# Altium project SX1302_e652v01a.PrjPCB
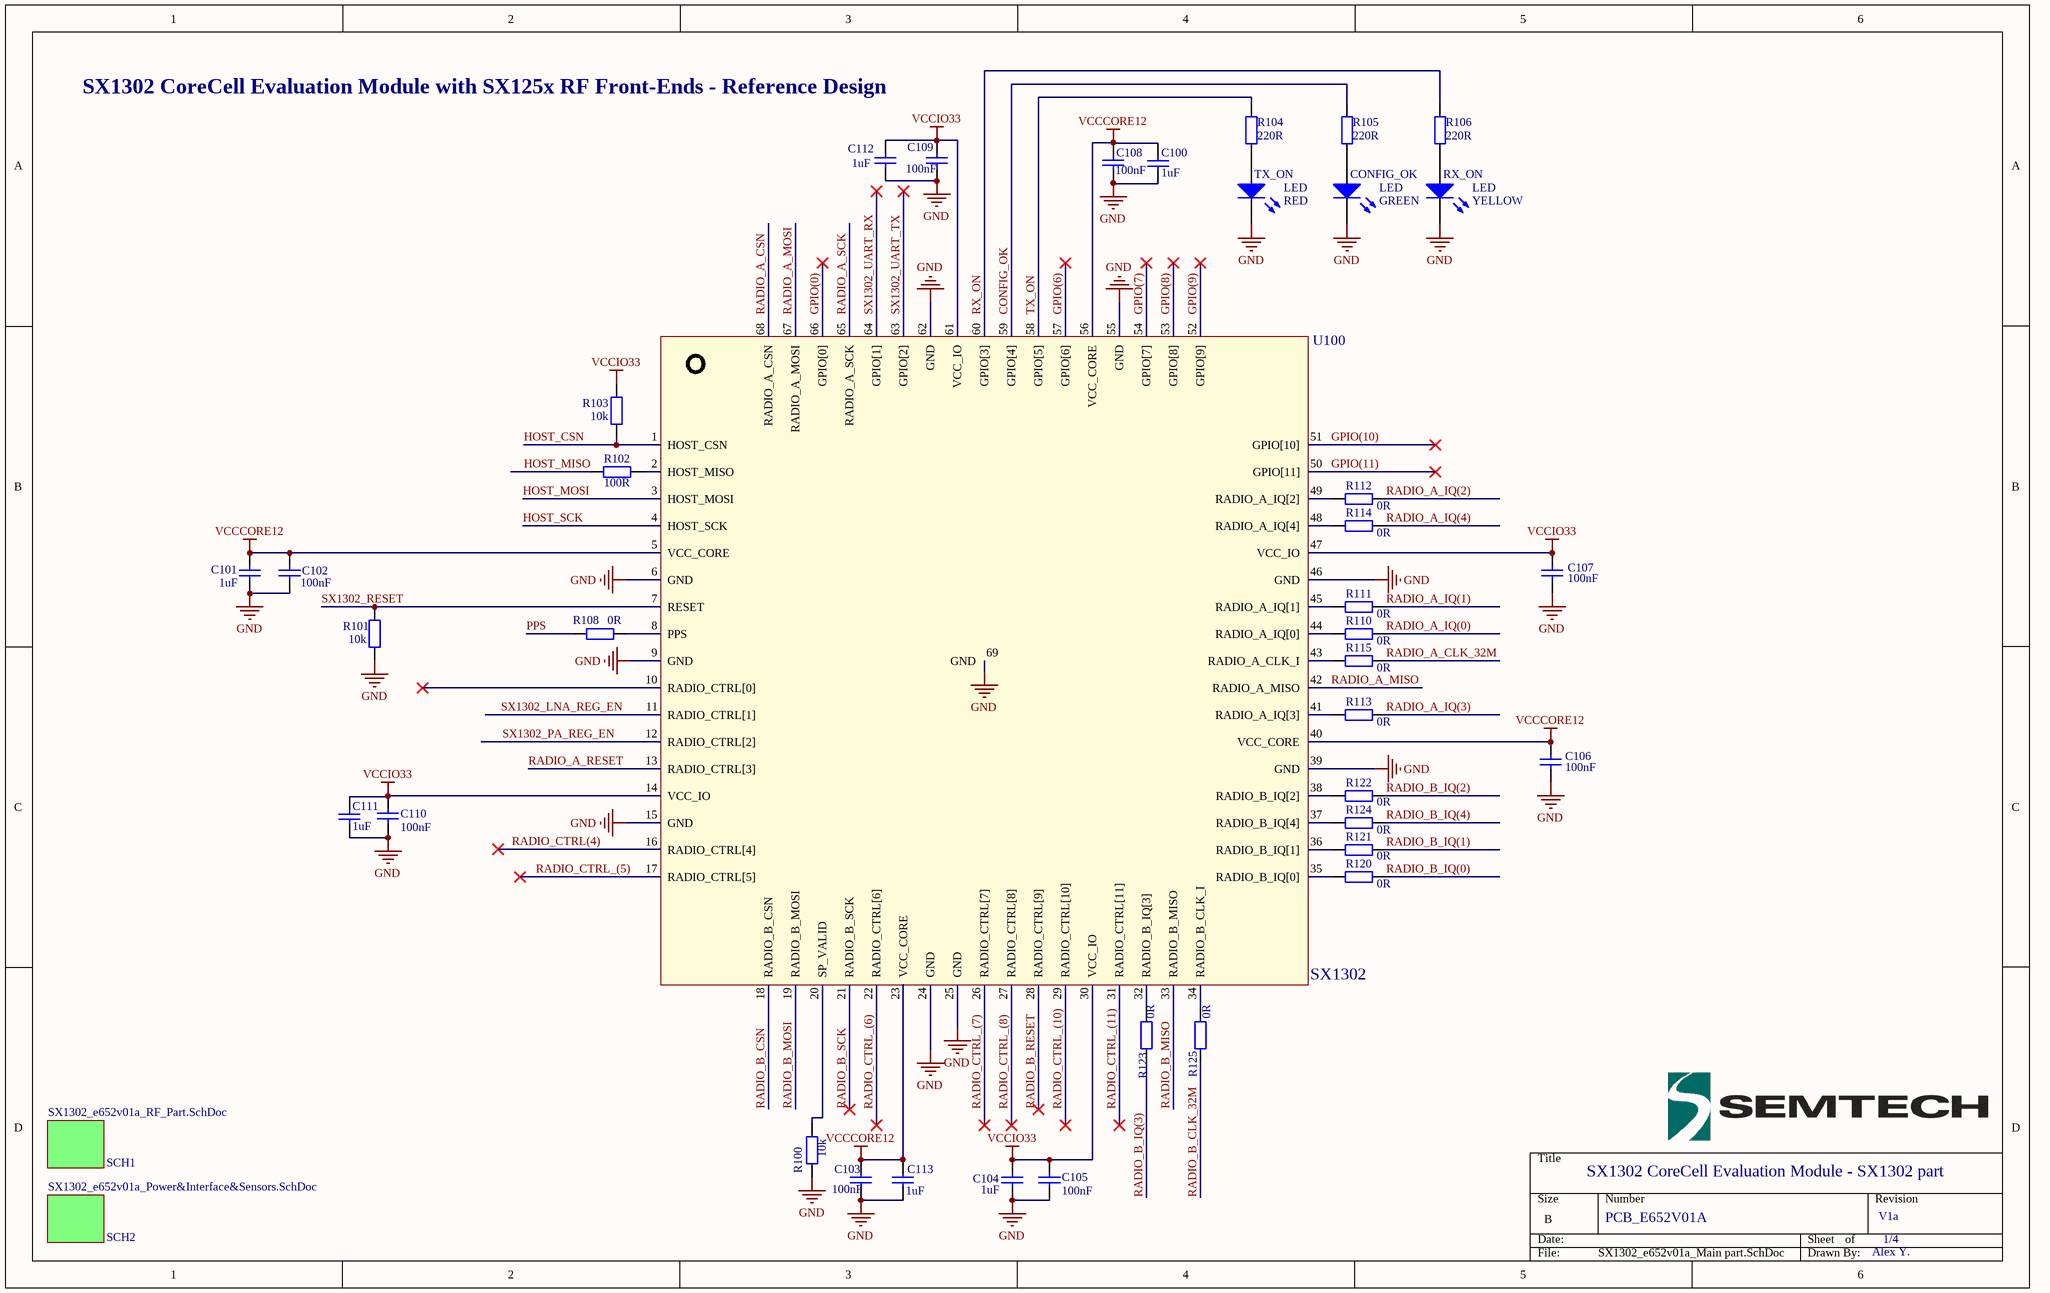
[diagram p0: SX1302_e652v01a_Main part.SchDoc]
4 sheets, 264 parts. Net scope: global (net labels, ports and power ports of the same name join across sheets).
Board file: SX1302_e652v01a.PcbDoc
Sheets:
  SX1302_e652v01a_Main part.SchDoc
    SCH2 = SX1302_e652v01a_Power&Interface&Sensors.SchDoc
    SCH1 = SX1302_e652v01a_RF_Part.SchDoc
       = SX1302_e652v01a_RF_PA.SchDoc

## Sheet SX1302_e652v01a_Main part.SchDoc: SX1302
size B; Author: Alex; DrawnBy: AYang; DocumentNumber: 1; SheetNumber: 1; SheetTotal: 5; PageSetup: Record=PageOptions¦CenterHorizontal=True¦CenterVertical=True¦PrintScale=0.72¦XCorrection=1.00¦YCorrection=1.00¦PrintKind=0¦BorderSize=5000000¦LeftOffset=0¦BottomOffset=0¦Orientation=2¦PaperLength=1000¦PaperWidth=1000¦Scale=100¦PaperSource=7¦PrintQuality=-4¦MediaType=1¦DitherType=10¦PaperKind=Letter¦PrintScaleMode=1

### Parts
C100  value 1uF  [rlc_402_smd_small]  (hidden comment: Cap)
C101  value 1uF  [rlc_402_smd_small]  (hidden comment: Cap)
C102  value 100nF  [rlc_201_smd_small]  (hidden comment: Cap)
C103  value 100nF  [rlc_201_smd_small]  (hidden comment: Cap)
C104  value 1uF  [rlc_402_smd_small]  (hidden comment: Cap)
C105  value 100nF  [rlc_201_smd_small]  (hidden comment: Cap)
C106  value 100nF  [rlc_201_smd_small]  (hidden comment: Cap)
C107  value 100nF  [rlc_201_smd_small]  (hidden comment: Cap)
C108  value 100nF  [rlc_201_smd_small]  (hidden comment: Cap)
C109  value 100nF  [rlc_201_smd_small]  (hidden comment: Cap)
C110  value 100nF  [rlc_201_smd_small]  (hidden comment: Cap)
C111  value 1uF  [rlc_402_smd_small]  (hidden comment: Cap)
C112  value 1uF  [rlc_402_smd_small]  (hidden comment: Cap)
C113  value 1uF  [rlc_402_smd_small]  (hidden comment: Cap)
CONFIG_OK  LED  Type: GREEN  [CD1005-0402]
R100  value 10k  [rlc_201_smd_small]  (hidden comment: Resistor)
R101  value 10k  [rlc_201_smd_small]  (hidden comment: Resistor)
R102  value 100R  [rlc_201_smd_small]  (hidden comment: Resistor)
R103  value 10k  [rlc_201_smd_small]  (hidden comment: Resistor)
R104  value 220R  [rlc_402_smd]  (hidden comment: Resistor)
R105  value 220R  [rlc_402_smd]  (hidden comment: Resistor)
R106  value 220R  [rlc_402_smd]  (hidden comment: Resistor)
R108  value 0R  [rlc_201_smd_small]  (hidden comment: Resistor)
R110  value 0R  [rlc_201_smd_small]  (hidden comment: Resistor)
R111  value 0R  [rlc_201_smd_small]  (hidden comment: Resistor)
R112  value 0R  [rlc_201_smd_small]  (hidden comment: Resistor)
R113  value 0R  [rlc_201_smd_small]  (hidden comment: Resistor)
R114  value 0R  [rlc_201_smd_small]  (hidden comment: Resistor)
R115  value 0R  [rlc_201_smd_small]  (hidden comment: Resistor)
R120  value 0R  [rlc_201_smd_small]  (hidden comment: Resistor)
R121  value 0R  [rlc_201_smd_small]  (hidden comment: Resistor)
R122  value 0R  [rlc_201_smd_small]  (hidden comment: Resistor)
R123  value 0R  [rlc_201_smd_small]  (hidden comment: Resistor)
R124  value 0R  [rlc_201_smd_small]  (hidden comment: Resistor)
R125  value 0R  [rlc_201_smd_small]  (hidden comment: Resistor)
RX_ON  LED  Type: YELLOW  [CD1005-0402]
TX_ON  LED  Type: RED  [CD1005-0402]
U100  SX1302  [vqfn68_7x7mm]

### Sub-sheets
SCH1 = SX1302_e652v01a_RF_Part.SchDoc: no entries
SCH2 = SX1302_e652v01a_Power&Interface&Sensors.SchDoc: no entries

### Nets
GND: C100.1 C101.1 C102.1 C103.1 C104.1 C105.1 C106.1 C107.1 C108.1 C109.1 C110.1 C111.1 C112.1 C113.1 CONFIG_OK.2(K) R100.1 R101.1 RX_ON.2(K) TX_ON.2(K) U100.6(GND) U100.9(GND) U100.15(GND) U100.24(GND) U100.25(GND) U100.39(GND) U100.46(GND) U100.55(GND) U100.62(GND) U100.69(GND)
VCCCORE12: C100.2 C101.2 C102.2 C103.2 C106.2 C108.2 C113.2 U100.5(VCC_CORE) U100.23(VCC_CORE) U100.40(VCC_CORE) U100.56(VCC_CORE)
VCCIO33: C104.2 C105.2 C107.2 C109.2 C110.2 C111.2 C112.2 R103.2 U100.14(VCC_IO) U100.30(VCC_IO) U100.47(VCC_IO) U100.61(VCC_IO)
CONFIG_OK: R105.2 U100.59(GPIO[4])
GPIO(0): U100.66(GPIO[0])
GPIO(6): U100.57(GPIO[6])
GPIO(7): U100.54(GPIO[7])
GPIO(8): U100.53(GPIO[8])
GPIO(9): U100.52(GPIO[9])
GPIO(10): U100.51(GPIO[10])
GPIO(11): U100.50(GPIO[11])
HOST_CSN: R103.1 U100.1(HOST_CSN)
HOST_MISO: R102.2
HOST_MOSI: U100.3(HOST_MOSI)
HOST_SCK: U100.4(HOST_SCK)
PPS: R108.1
RADIO_A_CLK_32M: R115.2
RADIO_A_CSN: U100.68(RADIO_A_CSN)
RADIO_A_IQ(0): R110.2
RADIO_A_IQ(1): R111.2
RADIO_A_IQ(2): R112.2
RADIO_A_IQ(3): R113.2
RADIO_A_IQ(4): R114.2
RADIO_A_MISO: U100.42(RADIO_A_MISO)
RADIO_A_MOSI: U100.67(RADIO_A_MOSI)
RADIO_A_RESET: U100.13(RADIO_CTRL[3])
RADIO_A_SCK: U100.65(RADIO_A_SCK)
RADIO_B_CLK_32M: R125.1
RADIO_B_CSN: U100.18(RADIO_B_CSN)
RADIO_B_IQ(0): R120.2
RADIO_B_IQ(1): R121.2
RADIO_B_IQ(2): R122.2
RADIO_B_IQ(3): R123.1
RADIO_B_IQ(4): R124.2
RADIO_B_MISO: U100.33(RADIO_B_MISO)
RADIO_B_MOSI: U100.19(RADIO_B_MOSI)
RADIO_B_RESET: U100.28(RADIO_CTRL[9])
RADIO_B_SCK: U100.21(RADIO_B_SCK)
RADIO_CTRL(4): U100.16(RADIO_CTRL[4])
RADIO_CTRL_(5): U100.17(RADIO_CTRL[5])
RADIO_CTRL_(6): U100.22(RADIO_CTRL[6])
RADIO_CTRL_(7): U100.26(RADIO_CTRL[7])
RADIO_CTRL_(8): U100.27(RADIO_CTRL[8])
RADIO_CTRL_(10): U100.29(RADIO_CTRL[10])
RADIO_CTRL_(11): U100.31(RADIO_CTRL[11])
RX_ON: R106.2 U100.60(GPIO[3])
SX1302_LNA_REG_EN: U100.11(RADIO_CTRL[1])
SX1302_PA_REG_EN: U100.12(RADIO_CTRL[2])
SX1302_RESET: R101.2 U100.7(RESET)
SX1302_UART_RX: U100.64(GPIO[1])
SX1302_UART_TX: U100.63(GPIO[2])
TX_ON: R104.2 U100.58(GPIO[5])
NetCONFIG_OK_1: CONFIG_OK.1(A) R105.1
NetR100_2: R100.2 U100.20(SP_VALID)
NetR102_1: R102.1 U100.2(HOST_MISO)
NetR104_1: R104.1 TX_ON.1(A)
NetR106_1: R106.1 RX_ON.1(A)
NetR108_2: R108.2 U100.8(PPS)
NetR110_1: R110.1 U100.44(RADIO_A_IQ[0])
NetR111_1: R111.1 U100.45(RADIO_A_IQ[1])
NetR112_1: R112.1 U100.49(RADIO_A_IQ[2])
NetR113_1: R113.1 U100.41(RADIO_A_IQ[3])
NetR114_1: R114.1 U100.48(RADIO_A_IQ[4])
NetR115_1: R115.1 U100.43(RADIO_A_CLK_I)
NetR120_1: R120.1 U100.35(RADIO_B_IQ[0])
NetR121_1: R121.1 U100.36(RADIO_B_IQ[1])
NetR122_1: R122.1 U100.38(RADIO_B_IQ[2])
NetR123_2: R123.2 U100.32(RADIO_B_IQ[3])
NetR124_1: R124.1 U100.37(RADIO_B_IQ[4])
NetR125_2: R125.2 U100.34(RADIO_B_CLK_I)

Not connected (* = marked no-connect by the designer): U100 10(RADIO_CTRL[0])*

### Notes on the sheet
- SX1302 CoreCell Evaluation Module with SX125x RF Front-Ends - Reference Design
- SX1302 CoreCell Evaluation Module - SX1302 part
- PCB_E652V01A
- V1a
- 1/4
- Alex Y.

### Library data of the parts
C100-C113 = Cap: Capacitor SMD
R100-R106 R108 R110-R115 R120-R125 = Resistor: Resistor SMD - IEC symbol version
U100 = SX1302: SX1302 - Base Band Processor for Data Concentrator for Long Range Communication Network;

## Sheet SX1302_e652v01a_Power&Interface&Sensors.SchDoc
size A2; DrawnBy: EMr; DocumentNumber: 2; SheetNumber: 2; SheetTotal: 5; PageSetup: Record=PageOptions¦CenterHorizontal=True¦CenterVertical=True¦PrintScale=0.72¦XCorrection=1.00¦YCorrection=1.00¦PrintKind=0¦BorderSize=5000000¦LeftOffset=0¦BottomOffset=0¦Orientation=2¦PaperLength=1000¦PaperWidth=1000¦Scale=100¦PaperSource=7¦PrintQuality=-4¦MediaType=1¦DitherType=10¦PaperKind=Letter¦PrintScaleMode=1
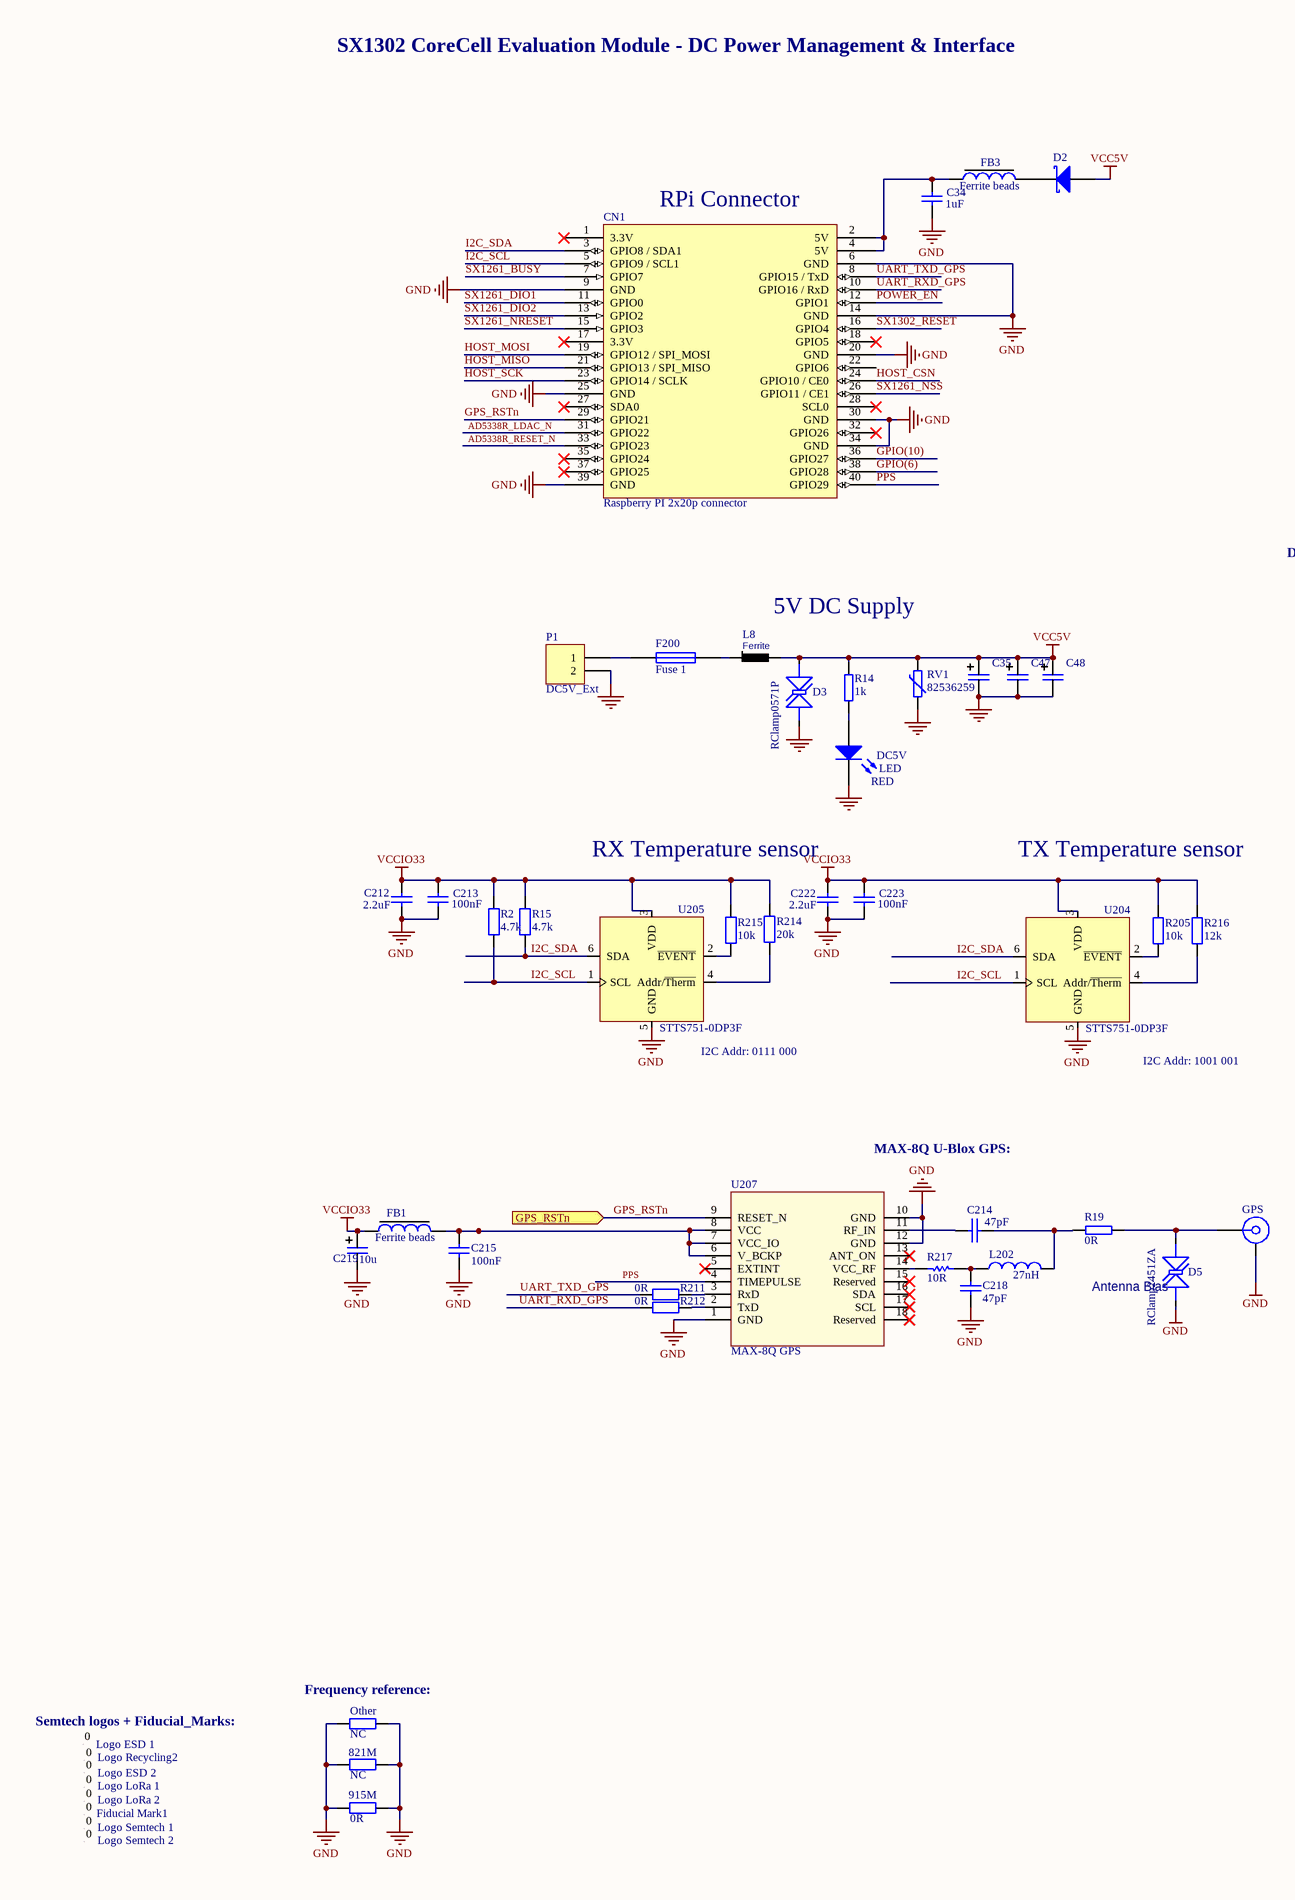
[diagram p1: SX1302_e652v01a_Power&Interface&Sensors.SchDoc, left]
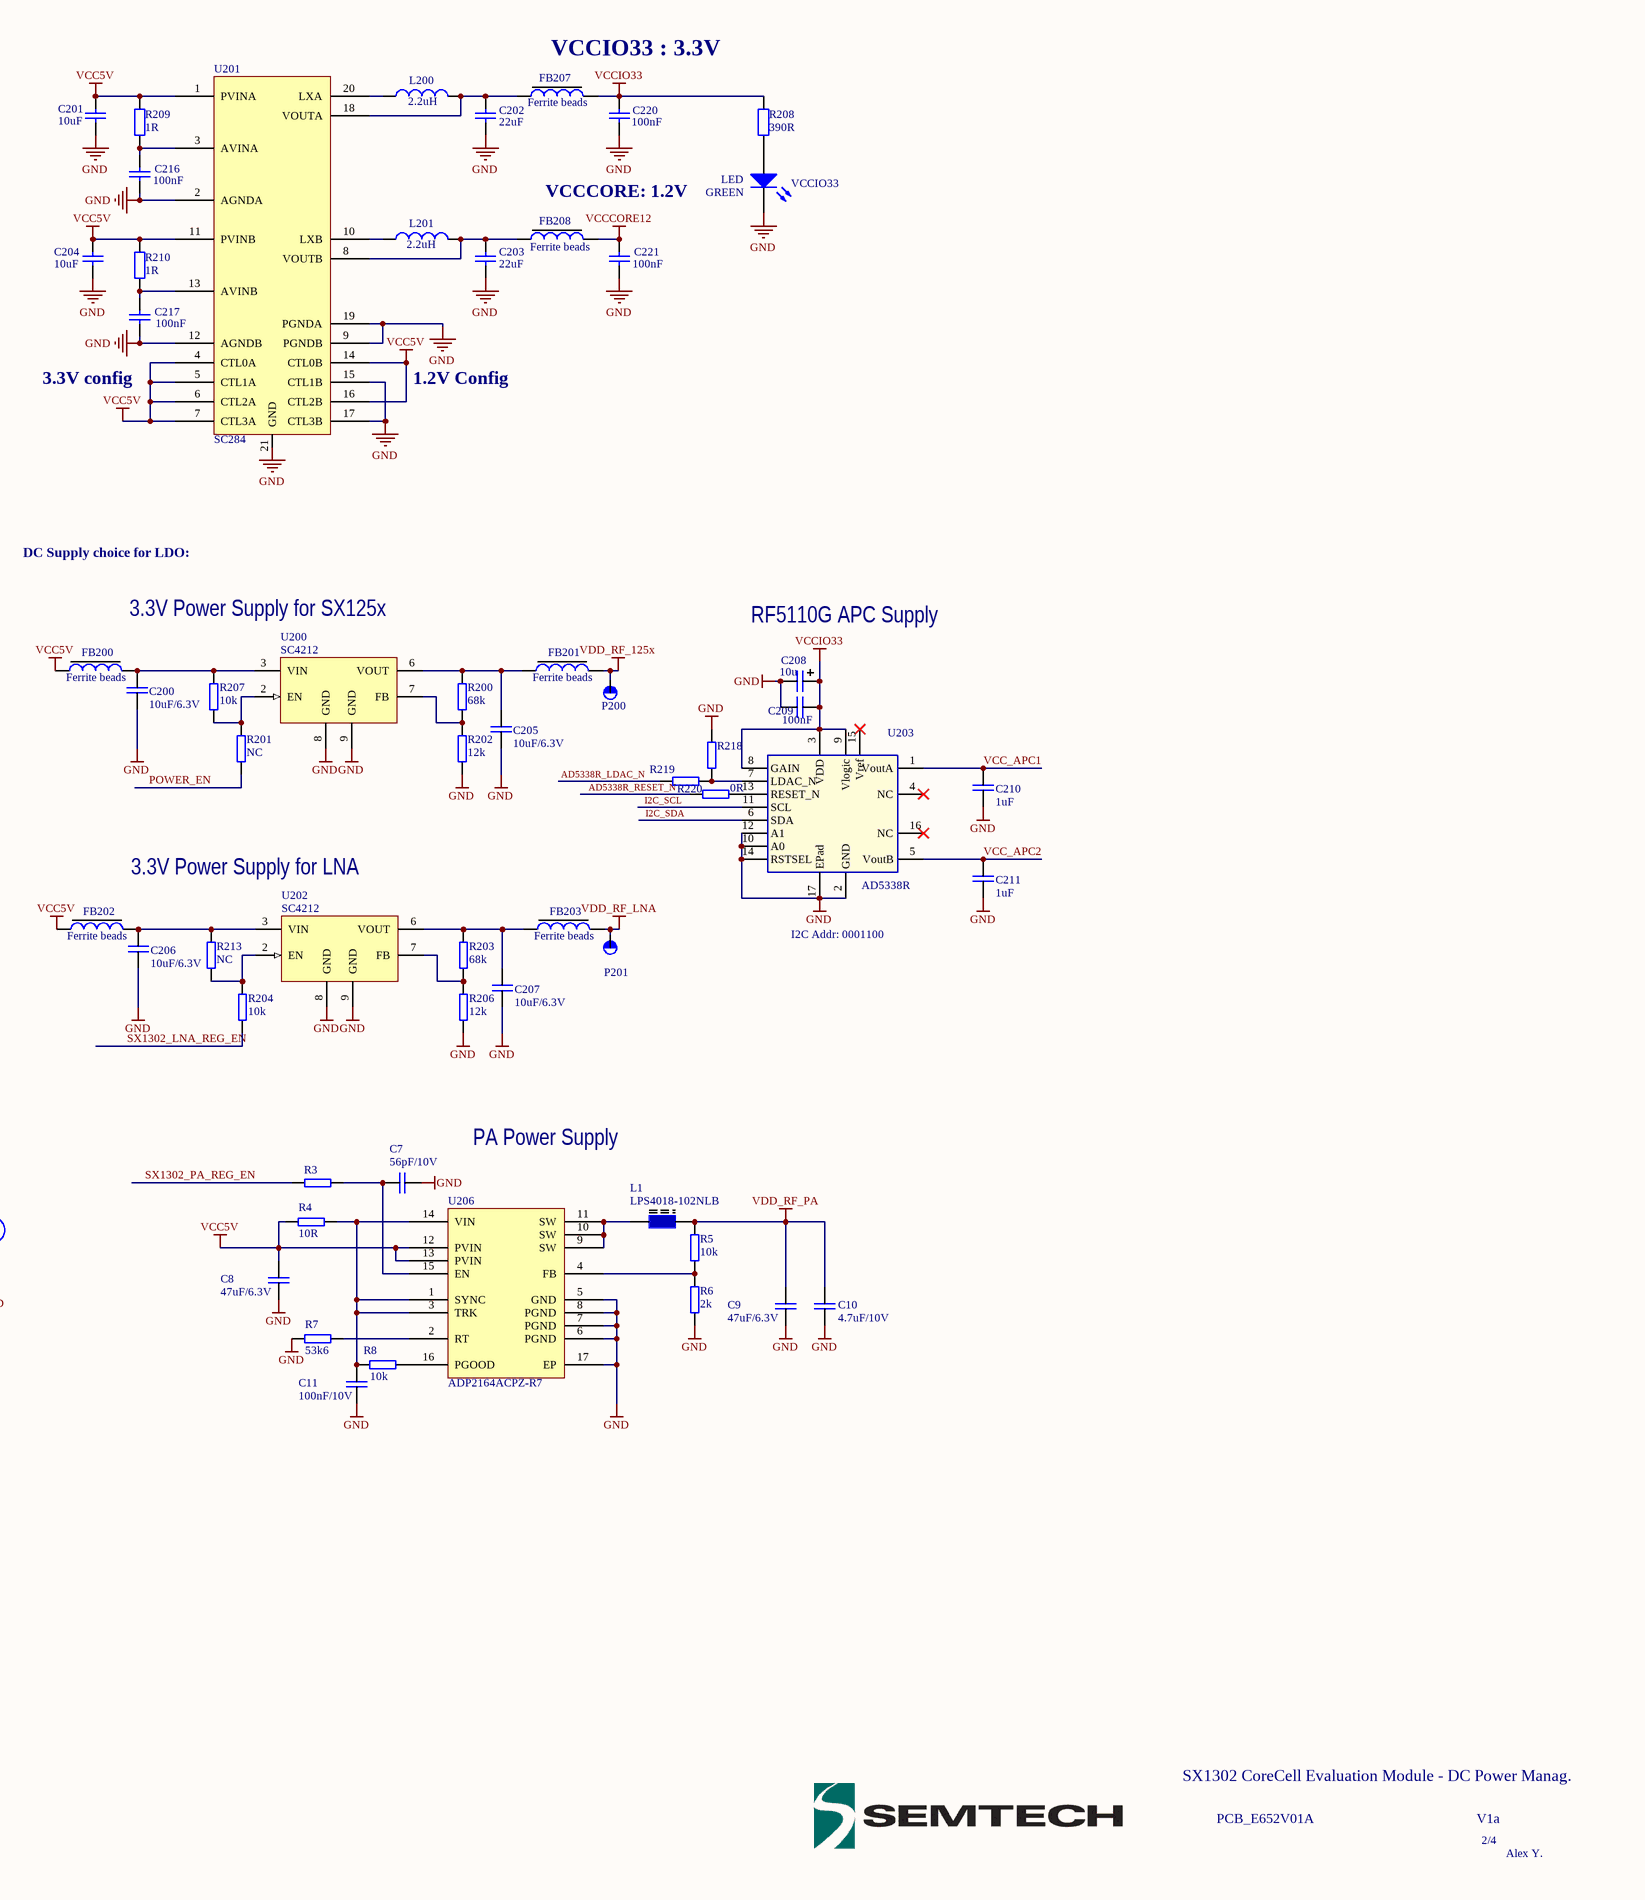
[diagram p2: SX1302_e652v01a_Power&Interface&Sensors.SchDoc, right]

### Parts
821M  value NC  [rlc_402_smd_small]  (hidden comment: Resistor)
915M  value 0R  [rlc_402_smd_small]  (hidden comment: Resistor)
C7  56pF/10V  [rlc_402_smd]
C8  47uF/6.3V  [1206]
C9  47uF/6.3V  [1206]
C10  4.7uF/10V  [rlc_805_smd]
C11  100nF/10V  [rlc_402_smd]
C34  value 1uF  [rlc_402_smd]  (hidden comment: Cap)
C35  293D127X96R3D2TE3  [C1206]  (value not drawn)
C47  293D127X96R3D2TE3  [rlc_805_smd]  (value not drawn)
C48  293D127X96R3D2TE3  [rlc_402_smd]  (value not drawn)
C200  10uF/6.3V  [rlc_603_smd]
C201  value 10uF  [rlc_805_smd]  (hidden comment: Cap)
C202  value 22uF  [rlc_805_smd]  (hidden comment: Cap)
C203  value 22uF  [rlc_805_smd]  (hidden comment: Cap)
C204  value 10uF  [rlc_805_smd]  (hidden comment: Cap)
C205  10uF/6.3V  [rlc_603_smd]
C206  10uF/6.3V  [rlc_603_smd]
C207  10uF/6.3V  [rlc_603_smd]
C208  10u  [rlc_805_smd]
C209  100nF  [rlc_402_smd]
C210  1uF  [rlc_402_smd]
C211  1uF  [rlc_402_smd]
C212  value 2.2uF  [rlc_603_smd_small]  (hidden comment: Cap)
C213  value 100nF  [rlc_402_smd_small]  (hidden comment: Cap)
C214  47pF  [rlc_402_smd]
C215  value 100nF  [rlc_402_smd]  (hidden comment: Cap)
C216  value 100nF  [rlc_402_smd_small]  (hidden comment: Cap)
C217  value 100nF  [rlc_402_smd_small]  (hidden comment: Cap)
C218  value 47pF  [rlc_402_smd]  (hidden comment: Cap)
C219  10u  [rlc_805_smd]
C220  value 100nF  [rlc_402_smd_small]  (hidden comment: Cap)
C221  value 100nF  [rlc_402_smd_small]  (hidden comment: Cap)
C222  value 2.2uF  [rlc_603_smd_small]  (hidden comment: Cap)
C223  value 100nF  [rlc_402_smd_small]  (hidden comment: Cap)
CN1  Raspberry PI 2x20p connector  [HDR2X20_Raspberry_PI_Reversed]
D2  D Schottky  [SOD123_INV]  (value not drawn)
D3  RClamp0571P  [1610]
D5  RClamp2451ZA  [SLP0603P]
DC5V  LED  Type: RED  [CD1005-0402]
F200  Fuse 1  [rlc_603_smd]
FB1  Ferrite beads  [rlc_402_smd_small]
FB3  Ferrite beads  [rlc_402_smd]
FB200  Ferrite beads  [rlc_402_smd_small]
FB201  Ferrite beads  [rlc_402_smd_small]
FB202  Ferrite beads  [rlc_402_smd_small]
FB203  Ferrite beads  [rlc_402_smd_small]
FB207  Ferrite beads  [rlc_402_smd_small]
FB208  Ferrite beads  [rlc_402_smd_small]
Fiducial_Mark1  Logo symbol  BOT  [fiducial_mark_signal_top]  (value not drawn)
GPS  32K242-40ML5  [ROS-32K242-40ML5_V _modified]  (value not drawn)
L1  LPS4018-102NLB  [L_4x4_COILCRAFT_LPS4018]
L8  BLM21SP700SH1D  [rlc_805_smd]  (value not drawn)
L200  value 2.2uH  [L4818]  (hidden comment: Inductor)
L201  value 2.2uH  [L4818]  (hidden comment: Inductor)
L202  value 27nH  [rlc_402_smd]  (hidden comment: Inductor)
Logo_ESD_1  Logo symbol  [ESD_small]  (value not drawn)
Logo_ESD_2  Logo symbol  [ESD_small]  (value not drawn)
Logo_LoRa_1  Logo symbol Bot  [Logo LoRa Size2]  (value not drawn)
Logo_LoRa_2  Logo symbol TOP  [Logo LoRa Size2]  (value not drawn)
Logo_Recycling2  Logo symbol  [Recycle1]  (value not drawn)
Logo_Semtech_1  Logo symbol TOP  [logo_semtech_horiz_size1]  (value not drawn)
Logo_Semtech_2  Logo Semtech  Bot2  [logo_semtech_horiz_size2]  (value not drawn)
Other  value NC  [rlc_402_smd_small]  (hidden comment: Resistor)
P1  DC5V_Ext  [3.81mm-2P-Female]
P200  Testpoint SMD  [TESTPUNKT_SMD_1mm]  (value not drawn)  (no BOM)
P201  Testpoint SMD  [TESTPUNKT_SMD_1mm]  (value not drawn)  (no BOM)
R2  value 4.7k  [rlc_402_smd]  (hidden comment: Resistor)
R3  100R  [rlc_402_smd]  (value not drawn)
R4  10R  [rlc_402_smd]
R5  10k  [rlc_402_smd]
R6  2k  [rlc_402_smd]
R7  53k6  [rlc_402_smd]
R8  10k  [rlc_402_smd]
R14  1k  [rlc_402_smd]
R15  value 4.7k  [rlc_402_smd]  (hidden comment: Resistor)
R19  0R  [rlc_402_smd]
R200  68k  [rlc_402_smd]
R201  NC  [rlc_402_smd]
R202  12k  [rlc_402_smd]
R203  68k  [rlc_402_smd]
R204  10k  [rlc_402_smd]
R205  value 10k  [rlc_402_smd]  (hidden comment: Resistor)
R206  12k  [rlc_402_smd]
R207  10k  [rlc_402_smd]
R208  value 390R  [rlc_402_smd]  (hidden comment: Resistor)
R209  value 1R  [rlc_402_smd_small]  (hidden comment: Resistor)
R210  value 1R  [rlc_402_smd_small]  (hidden comment: Resistor)
R211  value 0R  [rlc_402_smd]  (hidden comment: Resistor)
R212  value 0R  [rlc_402_smd]  (hidden comment: Resistor)
R213  NC  [rlc_402_smd]
R214  value 20k  [rlc_402_smd]  (hidden comment: Resistor)
R215  value 10k  [rlc_402_smd_small]  (hidden comment: Resistor)
R216  value 12k  [rlc_402_smd]  (hidden comment: Resistor)
R217  value 10R  [rlc_402_smd]  (hidden comment: Res1)
R218  0R  [rlc_402_smd]  (value not drawn)
R219  0R  [rlc_402_smd]  (value not drawn)
R220  0R  [rlc_402_smd]
RV1  82536259  [rlc_603_smd]
U200  SC4212  [MLPD-8 3x3mm]
U201  SC284  [MLPQ-UT-20 3x3]
U202  SC4212  [MLPD-8 3x3mm]
U203  AD5338R  [CP-16-22_M]
U204  STTS751-0DP3F  [UDFN-6L_2X2mm]
U205  STTS751-0DP3F  [UDFN-6L_2X2mm]
U206  ADP2164ACPZ-R7  [QFN127P600-8N]
U207  MAX-8Q GPS  [MAX-7]
VCCIO33  LED  Type: GREEN  [CD1005-0402]

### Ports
GPS_RSTn (in)

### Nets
GND: 821M.1 821M.2 915M.1 915M.2 C7.1 C8.1 C9.1 C10.1 C11.1 C34.2 C35.2 C47.2 C48.2 C200.2 C201.2 C202.2 C203.2 C204.2 C205.2 C206.2 C207.2 C208.2 C209.2 C210.2 C211.2 C212.2 C213.2 C215.2 C216.1 C217.1 C218.2 C219.2 C220.1 C221.1 C222.2 C223.2 CN1.6(GND) CN1.9(GND) CN1.14(GND) CN1.20(GND) CN1.25(GND) CN1.30(GND) CN1.34(GND) CN1.39(GND) D3.2(K) D5.2(K) DC5V.2(K) GPS.MP Other.1 Other.2 P1.2 R6.1 R7.1 R202.1 R206.1 R218.1 RV1.1 U200.8(GND) U200.9(GND) U201.2(AGNDA) U201.9(PGNDB) U201.12(AGNDB) U201.15(CTL1B) U201.17(CTL3B) U201.19(PGNDA) U201.21(GND) U202.8(GND) U202.9(GND) U203.2(GND) U203.10(A0) U203.12(A1) U203.14(RSTSEL) U203.17(EPad) U204.5(GND) U205.5(GND) U206.5(GND) U206.6(PGND) U206.7(PGND) U206.8(PGND) U206.17(EP) U207.1(GND) U207.10(GND) U207.12(GND) VCCIO33.2(K)
VCC5V: C8.2 C35.1 C47.1 C48.1 C201.1 C204.1 D2.2(A) D3.1(A) FB200.1 FB202.1 L8.2 R4.1 R14.2 R209.2 R210.2 RV1.2 U201.1(PVINA) U201.4(CTL0A) U201.5(CTL1A) U201.6(CTL2A) U201.7(CTL3A) U201.11(PVINB) U201.14(CTL0B) U201.16(CTL2B) U206.12(PVIN) U206.13(PVIN)
VCCCORE12: C221.2 FB208.2
VCCIO33: C208.1 C209.1 C212.1 C213.1 C219.1 C220.2 C222.1 C223.1 FB1.1 FB207.2 R2.2 R15.2 R205.2 R208.1 R214.2 R215.2 R216.2 U203.3(VDD) U203.8(GAIN) U203.9(Vlogic) U204.3(VDD) U205.3(VDD)
VDD_RF_125x: FB201.2 P200.1
VDD_RF_LNA: FB203.2 P201.1
VDD_RF_PA: C9.2 C10.2 L1.2 R5.2
AD5338R_LDAC_N: CN1.31(GPIO22) R219.2
AD5338R_RESET_N: CN1.33(GPIO23) R220.2
GPIO(6): CN1.38(GPIO28)
GPIO(10): CN1.36(GPIO27)
GPS_RSTn: CN1.29(GPIO21) U207.9(RESET_N) ; port GPS_RSTn
HOST_CSN: CN1.24(GPIO10_/_CE0)
HOST_MISO: CN1.21(GPIO13_/_SPI_MISO)
HOST_MOSI: CN1.19(GPIO12_/_SPI_MOSI)
HOST_SCK: CN1.23(GPIO14_/_SCLK)
I2C_SCL: CN1.5(GPIO9_/_SCL1) R2.1 U203.11(SCL) U204.1(SCL) U205.1(SCL)
I2C_SDA: CN1.3(GPIO8_/_SDA1) R15.1 U203.6(SDA) U204.6(SDA) U205.6(SDA)
POWER_EN: CN1.12(GPIO1) R201.2
PPS: CN1.40(GPIO29) U207.4(TIMEPULSE)
SX1261_BUSY: CN1.7(GPIO7)
SX1261_DIO1: CN1.11(GPIO0)
SX1261_DIO2: CN1.13(GPIO2)
SX1261_NRESET: CN1.15(GPIO3)
SX1261_NSS: CN1.26(GPIO11_/_CE1)
SX1302_LNA_REG_EN: R204.2
SX1302_PA_REG_EN: R3.2
SX1302_RESET: CN1.16(GPIO4)
UART_RXD_GPS: CN1.10(GPIO16_/_RxD) R212.2
UART_TXD_GPS: CN1.8(GPIO15_/_TxD) R211.2
VCC_APC1: C210.1 U203.1(VoutA)
VCC_APC2: C211.1 U203.5(VoutB)
NetC7_2: C7.2 R3.1 U206.15(EN)
NetC11_2: C11.2 R4.2 R8.1 U206.1(SYNC) U206.3(TRK) U206.14(VIN)
NetC34_1: C34.1 CN1.2(5V) CN1.4(5V) FB3.1
NetC200_1: C200.1 FB200.2 R207.1 U200.3(VIN)
NetC202_1: C202.1 FB207.1 L200.2 U201.18(VOUTA)
NetC203_1: C203.1 FB208.1 L201.2 U201.8(VOUTB)
NetC205_1: C205.1 FB201.1 R200.2 U200.6(VOUT)
NetC206_1: C206.1 FB202.2 R213.1 U202.3(VIN)
NetC207_1: C207.1 FB203.1 R203.2 U202.6(VOUT)
NetC214_1: C214.1 L202.1 R19.1
NetC214_2: C214.2 U207.11(RF_IN)
NetC215_1: C215.1 FB1.2 U207.6(V_BCKP) U207.7(VCC_IO) U207.8(VCC)
NetC216_2: C216.2 R209.1 U201.3(AVINA)
NetC217_2: C217.2 R210.1 U201.13(AVINB)
NetC218_1: C218.1 L202.2 R217.1
NetD2_1: D2.1(K) FB3.2
NetD5_1: D5.1(A) GPS.1 R19.2
NetDC5V_1: DC5V.1(A) R14.1
NetF200_1: F200.1 P1.1
NetF200_2: F200.2 L8.1
NetL1_1: L1.1 U206.9(SW) U206.10(SW) U206.11(SW)
NetL200_1: L200.1 U201.20(LXA)
NetL201_1: L201.1 U201.10(LXB)
NetR5_1: R5.1 R6.2 U206.4(FB)
NetR7_2: R7.2 U206.2(RT)
NetR8_2: R8.2 U206.16(PGOOD)
NetR200_1: R200.1 R202.2 U200.7(FB)
NetR201_1: R201.1 R207.2 U200.2(EN)
NetR203_1: R203.1 R206.2 U202.7(FB)
NetR204_1: R204.1 R213.2 U202.2(EN)
NetR205_1: R205.1 U204.2(~{EVENT})
NetR208_2: R208.2 VCCIO33.1(A)
NetR211_1: R211.1 U207.3(RxD)
NetR212_1: R212.1 U207.2(TxD)
NetR214_1: R214.1 U205.4(Addr/~{Therm})
NetR215_1: R215.1 U205.2(~{EVENT})
NetR216_1: R216.1 U204.4(Addr/~{Therm})
NetR217_2: R217.2 U207.14(VCC_RF)
NetR218_2: R218.2 R219.1 U203.7(LDAC_N)
NetR220_1: R220.1 U203.13(RESET_N)

Not connected (* = marked no-connect by the designer): CN1 1(3.3V)* 17(3.3V)* 18(GPIO5)* 22(GPIO6) 27(SDA0)* 28(SCL0)* 32(GPIO26)* 35(GPIO24)* 37(GPIO25)*; Fiducial_Mark1 0; Logo_ESD_1 0; Logo_ESD_2 0; Logo_LoRa_1 0; Logo_LoRa_2 0; Logo_Recycling2 0; Logo_Semtech_1 0; Logo_Semtech_2 0; U203 4(NC)* 15(Vref)* 16(NC)*; U207 5(EXTINT)* 13(ANT_ON)* 15(Reserved)* 16(SDA)* 17(SCL)* 18(Reserved)*

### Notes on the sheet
- SX1302 CoreCell Evaluation Module - DC Power Management & Interface
- VCCIO33 : 3.3V
- (near CN1) RPi Connector
- VCCCORE: 1.2V
- 3.3V config
- 1.2V Config
- DC Supply choice for LDO:
- 5V DC Supply
- 3.3V Power Supply for SX125x
- RF5110G APC Supply
- RX Temperature sensor
- TX Temperature sensor
- 3.3V Power Supply for LNA
- I2C Addr: 0001100
- (near U205) I2C Addr: 0111 000
- (near U204) I2C Addr: 1001 001
- PA Power Supply
- MAX-8Q U-Blox GPS:
- (near L202) Antenna Bias
- (near Logo_ESD_1) Semtech logos + Fiducial_Marks:
- (near Other) Frequency reference:
- SX1302 CoreCell Evaluation Module - DC Power Manag.
- PCB_E652V01A
- V1a
- 2/4
- Alex Y.

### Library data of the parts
821M 915M Other R2 R15 R205 R208-R212 R214-R216 = Resistor: Resistor SMD - IEC symbol version
C7-C11 = 70001226: Ceramic Capacitor SMD
C34 C201-C204 C212 C213 C215-C218 C220-C223 = Cap: Capacitor SMD
C35 C47 C48 = Capacitor_p: CAP TANT 120UF 6.3V; Manufacturer: Vishay; Replacement: EBV
C200 C205-C207 C209-C211 = 70001485: Ceramic Capacitor SMD
C208 C219 = Capacitor_p: CAP TANT 10UF 6.3V; Manufacturer: Vishay; Replacement: EBV
C214 = CAP: Ceramic Capacitor SMD
CN1 = RPI: Raspberry PI 2x20p connector - Header male or receptacle
D2 = D Schottky: Schottky Diode
D3 D5 = RClamp0531T: Ultra Low Capacitance 1-line ESD Protection
F200 = Fuse 1: Fuse
FB1 FB3 FB200-FB203 FB207 FB208 = Ferrite beads: Value: VAL?
Fiducial_Mark1 Logo_ESD_1 Logo_ESD_2 Logo_LoRa_1 Logo_LoRa_2 Logo_Recycling2 Logo_Semtech_1 Logo_Semtech_2 = Logo: Schematic symbol for Logo
GPS = 32K242-40ML5: SMA Right Angle Jack, Edge Mount, Up to 18 GHz, -65 to 165 degC; Design Note 1: Footprint in library is a generic example - only application specific footprint delivers High Performance; Desgin Note 2: For more information about DRC setting, please look at following webpage, http://techdocs.altium.com/display/SCRT/Design+Rule+for+Edge-Mount+Connectors
L1 = L_LPS4018-102NLB: Shielded Power Inductor 1uH isat 2.5A; Manufacturer: Coilcraft
L8 = L_FBMH4532HM681: Ferrite Bed 680 Ohm 1812; Manufacturer: Tayio Yuden; Replacement: Yes
L200 L201 = Inductor: Code_IEC: 1005
L202 = Inductor: Inductor SMD; Code_IEC: 1005
P1 = Header 2: Header, 2-Pin
P200 P201 = Testpunkt SMD
R3-R8 R14 R19 R200-R204 R206 R207 R213 R218-R220 = Res: SMD Resistor
R217 = Res1: Resistor
RV1 = RV_82536259: Varistor 5.5V 0603; Manufacturer: Würth; Replacement: Yes
U200 U202 = SC4212: SC4212 - Very Low Input /Very Low Dropout  1Amp Regulator With Enable; Manufacturer: Semtech; Replacement: None
U201 = SC284: SC284 - Dual Channel 2.5MHz, 1.8A  Synchronous Step-Down Regulator
U204 U205 = STTS751: 2.25 V low-voltage local digital temperature sensor
U206 = ADP2164ACPZ-R7: 6.5 V, 4 A, High Efficiency,   Step-Down DC-to-DC Regulator; Manufacturer: Analog Devices; Replacement: None
U207 = MAX-7Q: MAX-7Q; U-Blox; 7 GPS/GNSS modules

## Sheet SX1302_e652v01a_RF_Part.SchDoc: SX1308 Picocell V1.5 Gateway
size A2; DrawnBy: EMr; DocumentNumber: 3; SheetNumber: 3; SheetTotal: 5; PageSetup: Record=PageOptions¦CenterHorizontal=True¦CenterVertical=True¦PrintScale=0.47¦XCorrection=1.00¦YCorrection=1.00¦PrintKind=0¦BorderSize=5000000¦LeftOffset=0¦BottomOffset=0¦Orientation=2¦PaperLength=1000¦PaperWidth=1000¦Scale=100¦PaperSource=7¦PrintQuality=-4¦MediaType=1¦DitherType=10¦PaperKind=Letter¦PrintScaleMode=1
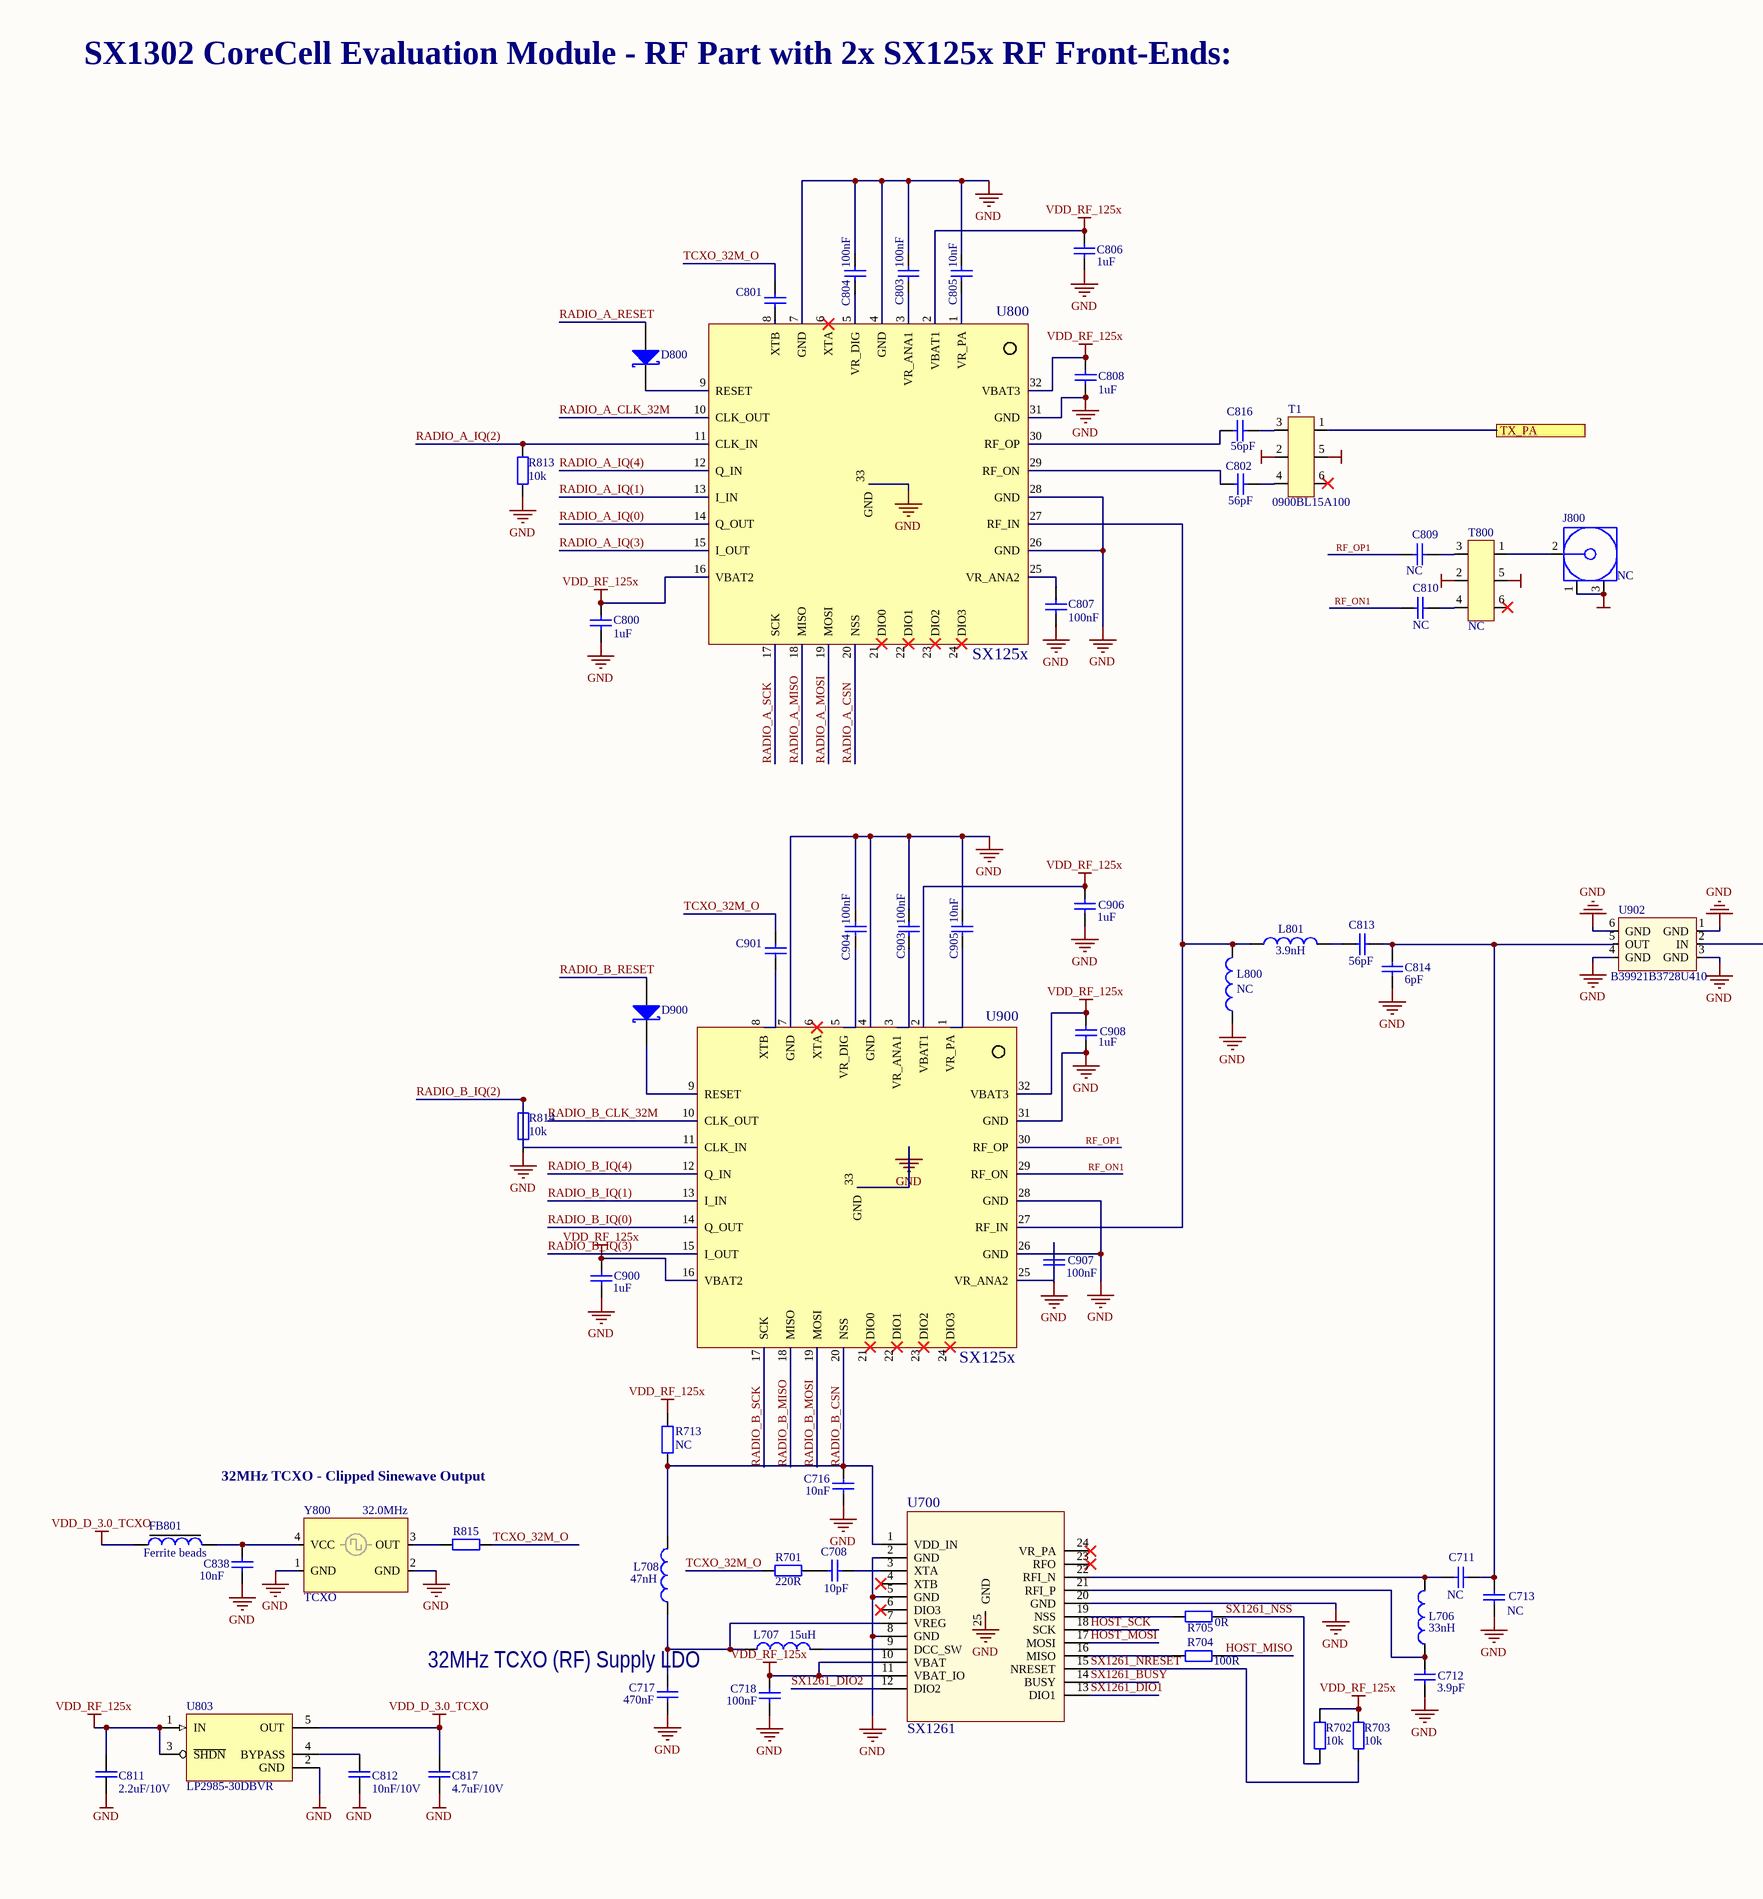
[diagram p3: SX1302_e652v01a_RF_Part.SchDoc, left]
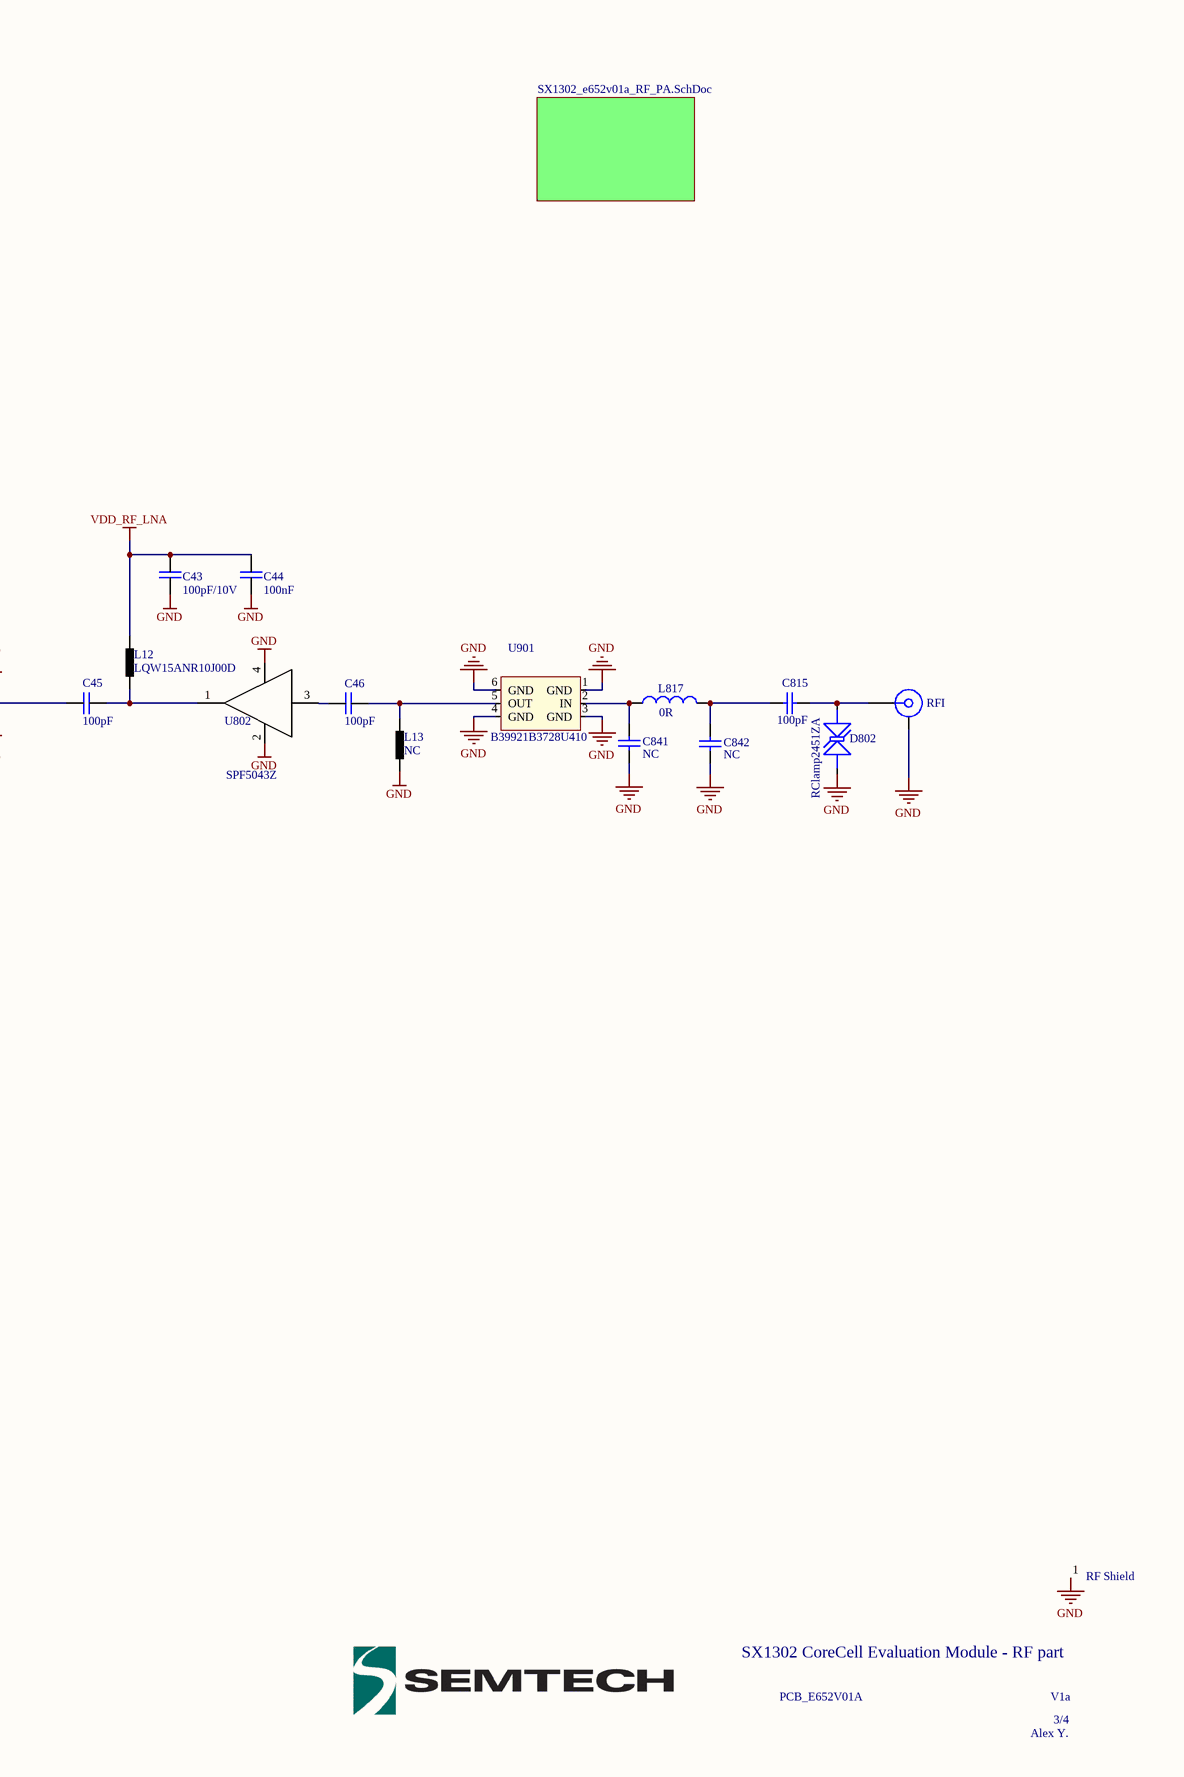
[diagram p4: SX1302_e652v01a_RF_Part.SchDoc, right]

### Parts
C43  100pF/10V  [rlc_402_smd]
C44  100nF  [rlc_402_smd]
C45  100pF  [rlc_402_smd]
C46  100pF  [rlc_402_smd]
C708  value 10pF  [rlc_201_smd_small]  (hidden comment: Cap)
C711  value NC  [rlc_402_smd_small]  (hidden comment: Cap)
C712  value 3.9pF  [rlc_402_smd_small]  (hidden comment: Cap)
C713  value NC  [rlc_402_smd_small]  (hidden comment: Cap)
C716  value 10nF  [rlc_402_smd_small]  (hidden comment: Cap)
C717  value 470nF  [rlc_402_smd_small]  (hidden comment: Cap)
C718  value 100nF  [rlc_402_smd_small]  (hidden comment: Cap)
C800  value 1uF  [rlc_402_smd_small]  (hidden comment: Cap)
C801  Cap  [rlc_201_smd_small]  (value not drawn)
C802  value 56pF  [rlc_402_smd_small]  (hidden comment: Cap)
C803  value 100nF  [rlc_201_smd_small]  (hidden comment: Cap)
C804  value 100nF  [rlc_201_smd_small]  (hidden comment: Cap)
C805  value 10nF  [rlc_201_smd_small]  (hidden comment: Cap)
C806  value 1uF  [rlc_402_smd_small]  (hidden comment: Cap)
C807  value 100nF  [rlc_201_smd_small]  (hidden comment: Cap)
C808  value 1uF  [rlc_402_smd_small]  (hidden comment: Cap)
C809  value NC  [rlc_201_smd]  (hidden comment: Cap)
C810  value NC  [rlc_201_smd]  (hidden comment: Cap)
C811  2.2uF/10V  [rlc_402_smd]
C812  10nF/10V  [rlc_402_smd]
C813  value 56pF  [rlc_402_smd_small]  (hidden comment: Cap)
C814  value 6pF  [rlc_402_smd_small]  (hidden comment: Cap)
C815  value 100pF  [rlc_402_smd_small]  (hidden comment: Cap)
C816  value 56pF  [rlc_402_smd_small]  (hidden comment: Cap)
C817  4.7uF/10V  [rlc_603_smd]
C838  value 10nF  [rlc_201_smd_small]  (hidden comment: Cap)
C841  value NC  [rlc_402_smd_small]  (hidden comment: Cap)
C842  value NC  [rlc_402_smd_small]  (hidden comment: Cap)
C900  value 1uF  [rlc_402_smd_small]  (hidden comment: Cap)
C901  Cap  [rlc_201_smd_small]  (value not drawn)
C903  value 100nF  [rlc_201_smd_small]  (hidden comment: Cap)
C904  value 100nF  [rlc_201_smd_small]  (hidden comment: Cap)
C905  value 10nF  [rlc_201_smd_small]  (hidden comment: Cap)
C906  value 1uF  [rlc_402_smd_small]  (hidden comment: Cap)
C907  value 100nF  [rlc_201_smd_small]  (hidden comment: Cap)
C908  value 1uF  [rlc_402_smd_small]  (hidden comment: Cap)
D800  D Schottky  [SOD523]  (value not drawn)
D802  RClamp2451ZA  [SLP0603P]
D900  D Schottky  [SOD523]  (value not drawn)
FB801  Ferrite beads  [rlc_402_smd_small]
J800  NC  [TECO-1909763-1_V]
L12  LQW15ANR10J00D  [rlc_402_smd]
L13  NC  [rlc_402_smd]
L706  value 33nH  [rlc_402_smd_small]  (hidden comment: Inductor)
L707  value 15uH  [rlc_805_smd_small]  (hidden comment: Inductor)
L708  value 47nH  [rlc_402_smd_small]  (hidden comment: Inductor)
L800  value NC  [rlc_402_smd_small]  (hidden comment: Inductor)
L801  value 3.9nH  [rlc_402_smd_small]  (hidden comment: Inductor)
L817  value 0R  [rlc_402_smd_small]  (hidden comment: Inductor)
R701  value 220R  [rlc_201_smd_small]  (hidden comment: Resistor)
R702  value 10k  [rlc_201_smd_small]  (hidden comment: Resistor)
R703  value 10k  [rlc_201_smd_small]  (hidden comment: Resistor)
R704  value 100R  [rlc_201_smd_small]  (hidden comment: Resistor)
R705  value 0R  [rlc_201_smd_small]  (hidden comment: Resistor)
R713  value NC  [rlc_201_smd_small]  (hidden comment: Resistor)
R813  value 10k  [rlc_201_smd_small]  (hidden comment: Resistor)
R814  value 10k  [rlc_201_smd_small]  (hidden comment: Resistor)
R815  Resistor  [rlc_201_smd_small]  (value not drawn)
RF_Shield  RF Shield  [SMS-461 - Shield - Custom]  (value not drawn)
RFI  32K242-40ML5  [ROS-32K242-40ML5_V _modified]  (value not drawn)
T1  PN: 0900BL15A100  [HHM Series 0805]  (hidden comment: Balun)
T800  NC  [HHM Series 0805]
U700  SX1261  [vqfn24_4x4mm]
U800  SX125x  [vqfn32_5x5mm]
U802  SPF5043Z  [SOT-343]
U803  LP2985-30DBVR  [SOT23-5]
U900  SX125x  [vqfn32_5x5mm]
U901  PN: B39921B3728U410  [DCC6C_3.0x3.0mm]  (hidden comment: SAW Filter)
U902  PN: B39921B3728U410  [DCC6C_3.0x3.0mm]  (hidden comment: SAW Filter)
Y800  TCXO  value 32.0MHz  [TCXO 2.0x1.6mm]

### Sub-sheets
? = SX1302_e652v01a_RF_PA.SchDoc: no entries

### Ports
TX_PA

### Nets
GND: C43.1 C44.1 C712.1 C713.1 C716.1 C717.1 C718.1 C800.1 C803.1 C804.2 C805.2 C806.1 C807.1 C808.1 C811.1 C812.1 C814.2 C817.1 C838.1 C841.2 C842.2 C900.1 C903.1 C904.2 C905.2 C906.1 C907.1 C908.1 D802.2(K) J800.1 J800.3 L13.1 L800.1 R813.2 R814.2 RF_Shield.1 RFI.MP T1.2(GND/DC_Feed) T1.5(GND) T800.2(GND/DC_Feed) T800.5(GND) U700.2(GND) U700.5(GND) U700.8(GND) U700.20(GND) U700.25(GND) U800.4(GND) U800.7(GND) U800.26(GND) U800.28(GND) U800.31(GND) U800.33(GND) U802.2(GND1) U802.4(GND2) U803.2(GND) U900.4(GND) U900.7(GND) U900.26(GND) U900.28(GND) U900.31(GND) U900.33(GND) U901.1(GND) U901.3(GND) U901.4(GND) U901.6(GND) U902.1(GND) U902.3(GND) U902.4(GND) U902.6(GND) Y800.1(GND) Y800.2(GND)
VDD_D_3.0_TCXO: C817.2 FB801.1 U803.5(OUT)
VDD_RF_125x: C718.2 C800.2 C806.2 C808.2 C811.2 C900.2 C906.2 C908.2 R702.1 R703.1 R713.1 U700.10(VBAT) U700.11(VBAT_IO) U800.2(VBAT1) U800.16(VBAT2) U800.32(VBAT3) U803.1(IN) U803.3(~{SHDN}) U900.2(VBAT1) U900.16(VBAT2) U900.32(VBAT3)
VDD_RF_LNA: C43.2 C44.2 L12.2
HOST_MISO: R704.2
HOST_MOSI: U700.17(MOSI)
HOST_SCK: U700.18(SCK)
RADIO_A_CLK_32M: U800.10(CLK_OUT)
RADIO_A_CSN: U800.20(NSS)
RADIO_A_IQ(0): U800.14(Q_OUT)
RADIO_A_IQ(1): U800.13(I_IN)
RADIO_A_IQ(2): R813.1 U800.11(CLK_IN)
RADIO_A_IQ(3): U800.15(I_OUT)
RADIO_A_IQ(4): U800.12(Q_IN)
RADIO_A_MISO: U800.18(MISO)
RADIO_A_MOSI: U800.19(MOSI)
RADIO_A_RESET: D800.2(A)
RADIO_A_SCK: U800.17(SCK)
RADIO_B_CLK_32M: U900.10(CLK_OUT)
RADIO_B_CSN: C716.2 L708.1 R713.2 U700.1(VDD_IN) U900.20(NSS)
RADIO_B_IQ(0): U900.14(Q_OUT)
RADIO_B_IQ(1): U900.13(I_IN)
RADIO_B_IQ(2): R814.1 U900.11(CLK_IN)
RADIO_B_IQ(3): U900.15(I_OUT)
RADIO_B_IQ(4): U900.12(Q_IN)
RADIO_B_MISO: U900.18(MISO)
RADIO_B_MOSI: U900.19(MOSI)
RADIO_B_RESET: D900.2(A)
RADIO_B_SCK: U900.17(SCK)
RF_ON1: C810.1 U900.29(RF_ON)
RF_OP1: C809.1 U900.30(RF_OP)
SX1261_BUSY: U700.14(BUSY)
SX1261_DIO1: U700.13(DIO1)
SX1261_DIO2: U700.12(DIO2)
SX1261_NRESET: R703.2 U700.15(NRESET)
SX1261_NSS: R702.2 R705.2
TCXO_32M_O: C801.1 C901.2 R701.2 R815.1
TX_PA: T1.1(UNBAL_Port) ; port TX_PA
NetC45_1: C45.1 L12.1 U802.1(OUT)
NetC45_2: C45.2 U902.2(IN)
NetC46_1: C46.1 L13.2 U901.5(OUT)
NetC46_2: C46.2 U802.3(IN)
NetC708_1: C708.1 U700.3(XTA)
NetC708_2: C708.2 R701.1
NetC711_1: C711.1 C713.2 C813.2 C814.1 U902.5(OUT)
NetC711_2: C711.2 L706.2 U700.22(RFI_N)
NetC712_2: C712.2 L706.1 U700.21(RFI_P)
NetC717_2: C717.2 L707.1 L708.2 U700.7(VREG)
NetC801_2: C801.2 U800.8(XTB)
NetC802_1: C802.1 U800.29(RF_ON)
NetC802_2: C802.2 T1.4(BAL_Port)
NetC803_2: C803.2 U800.3(VR_ANA1)
NetC804_1: C804.1 U800.5(VR_DIG)
NetC805_1: C805.1 U800.1(VR_PA)
NetC807_2: C807.2 U800.25(VR_ANA2)
NetC809_2: C809.2 T800.3(BAL_Port)
NetC810_2: C810.2 T800.4(BAL_Port)
NetC812_2: C812.2 U803.4(BYPASS)
NetC813_1: C813.1 L801.2
NetC815_1: C815.1 C842.1 L817.2
NetC815_2: C815.2 D802.1(A) RFI.1
NetC816_1: C816.1 U800.30(RF_OP)
NetC816_2: C816.2 T1.3(BAL_Port)
NetC838_2: C838.2 FB801.2 Y800.4(VCC)
NetC841_1: C841.1 L817.1 U901.2(IN)
NetC901_1: C901.1 U900.8(XTB)
NetC903_2: C903.2 U900.3(VR_ANA1)
NetC904_1: C904.1 U900.5(VR_DIG)
NetC905_1: C905.1 U900.1(VR_PA)
NetC907_2: C907.2 U900.25(VR_ANA2)
NetD800_1: D800.1(K) U800.9(RESET)
NetD900_1: D900.1(K) U900.9(RESET)
NetJ800_2: J800.2 T800.1(UNBAL_Port)
NetL707_2: L707.2 U700.9(DCC_SW)
NetL800_2: L800.2 L801.1 U800.27(RF_IN) U900.27(RF_IN)
NetR704_1: R704.1 U700.16(MISO)
NetR705_1: R705.1 U700.19(NSS)
NetR815_2: R815.2 Y800.3(OUT)

Not connected (* = marked no-connect by the designer): T1 6(NC)*; T800 6(NC)*; U700 4(XTB)* 6(DIO3)* 23(RFO)* 24(VR_PA)*; U800 6(XTA)* 21(DIO0)* 22(DIO1)* 23(DIO2)* 24(DIO3)*; U900 6(XTA)* 21(DIO0)* 22(DIO1)* 23(DIO2)* 24(DIO3)*

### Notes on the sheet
- SX1302 CoreCell Evaluation Module - RF Part with 2x SX125x RF Front-Ends:
- 32MHz TCXO - Clipped Sinewave Output
- 32MHz TCXO (RF) Supply LDO
- SX1302 CoreCell Evaluation Module - RF part
- PCB_E652V01A
- Alex Y.
- V1a
- 3/4

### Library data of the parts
C43-C46 = 70001226: Ceramic Capacitor SMD
C708 C711-C713 C716-C718 C800 C802-C810 C813-C816 C838 C841 C842 C900 C903-C908 = Cap: Capacitor SMD
C801 C901 = Cap: Capacitor SMD; Value: 1nF
C811 C812 C817 = 70001485: Ceramic Capacitor SMD
D800 D900 = D Schottky: Schottky Diode
D802 = RClamp0531T: as D3 on sheet SX1302_e652v01a_Power&Interface&Sensors
FB801 = Ferrite beads: Value: VAL?
J800 = 1909763-1: Ultra Miniature Coaxial Connector Jack, 60 V, 50 Ohm, -40 to 90 degC, RoHS, Tape and Reel; Brand: TE Connectivity / AMP; Maximum Frequency: 6 GHz; Gender: Jack (Female); Body Material: Liquid Crystal Polymer (LCP); RF Series: UMCC; Impedance: 50 Ohms
L12 = L_LQW15ANR10J00D_100NH_0402: 100nH Inductance wirewound 0402; Manufacturer: Murata; Replacement: Yes
L13 = L_LQW15AN10NJ80D_10NH_0402: 10nH Inductance wirewound 0402; Manufacturer: Murata; Replacement: Yes
L706-L708 L800 L801 L817 = Inductor: Code_IEC: 1005
R701-R705 R713 R813 R814 = Resistor: Resistor SMD - IEC symbol version
R815 = Resistor: Resistor SMD - IEC symbol version; Value: 150R
RF_Shield = Shield: RF Shield - EMI Gasket - Standard Surface Mount Shields
RFI = 32K242-40ML5: as GPS on sheet SX1302_e652v01a_Power&Interface&Sensors
T1 T800 = T_BALUN_HHM1564A4: High Frequency Balun - TDK HHM Series; 490MHz MPN: HHM1591D1
U700 = SX126x: SX1261/2 - Ultra low power RF transceiver
U800 U900 = SX1257: SX1257 RF Front-End Transceiver - I/Q New Pinout
U802 = SPF5043Z: Low Noise Amplifier; Manufacturer: RFMD; Replacement: TBD
U803 = LP2985-33: LDO 150mA w/ Enable; Manufacturer: TI; Replacement: None
U901 U902 = SAW Filter: SAW Filter - Bandpass - TEMEX type; value: 3x3mm

## Sheet SX1302_e652v01a_RF_PA.SchDoc: SX1308 Picocell V1.5 Gateway
size A3; DrawnBy: EMr; DocumentNumber: 4; SheetNumber: 4; SheetTotal: 5; PageSetup: Record=PageOptions¦CenterHorizontal=True¦CenterVertical=True¦PrintScale=0.47¦XCorrection=1.00¦YCorrection=1.00¦PrintKind=0¦BorderSize=5000000¦LeftOffset=0¦BottomOffset=0¦Orientation=2¦PaperLength=1000¦PaperWidth=1000¦Scale=100¦PaperSource=7¦PrintQuality=-4¦MediaType=1¦DitherType=10¦PaperKind=Letter¦PrintScaleMode=1
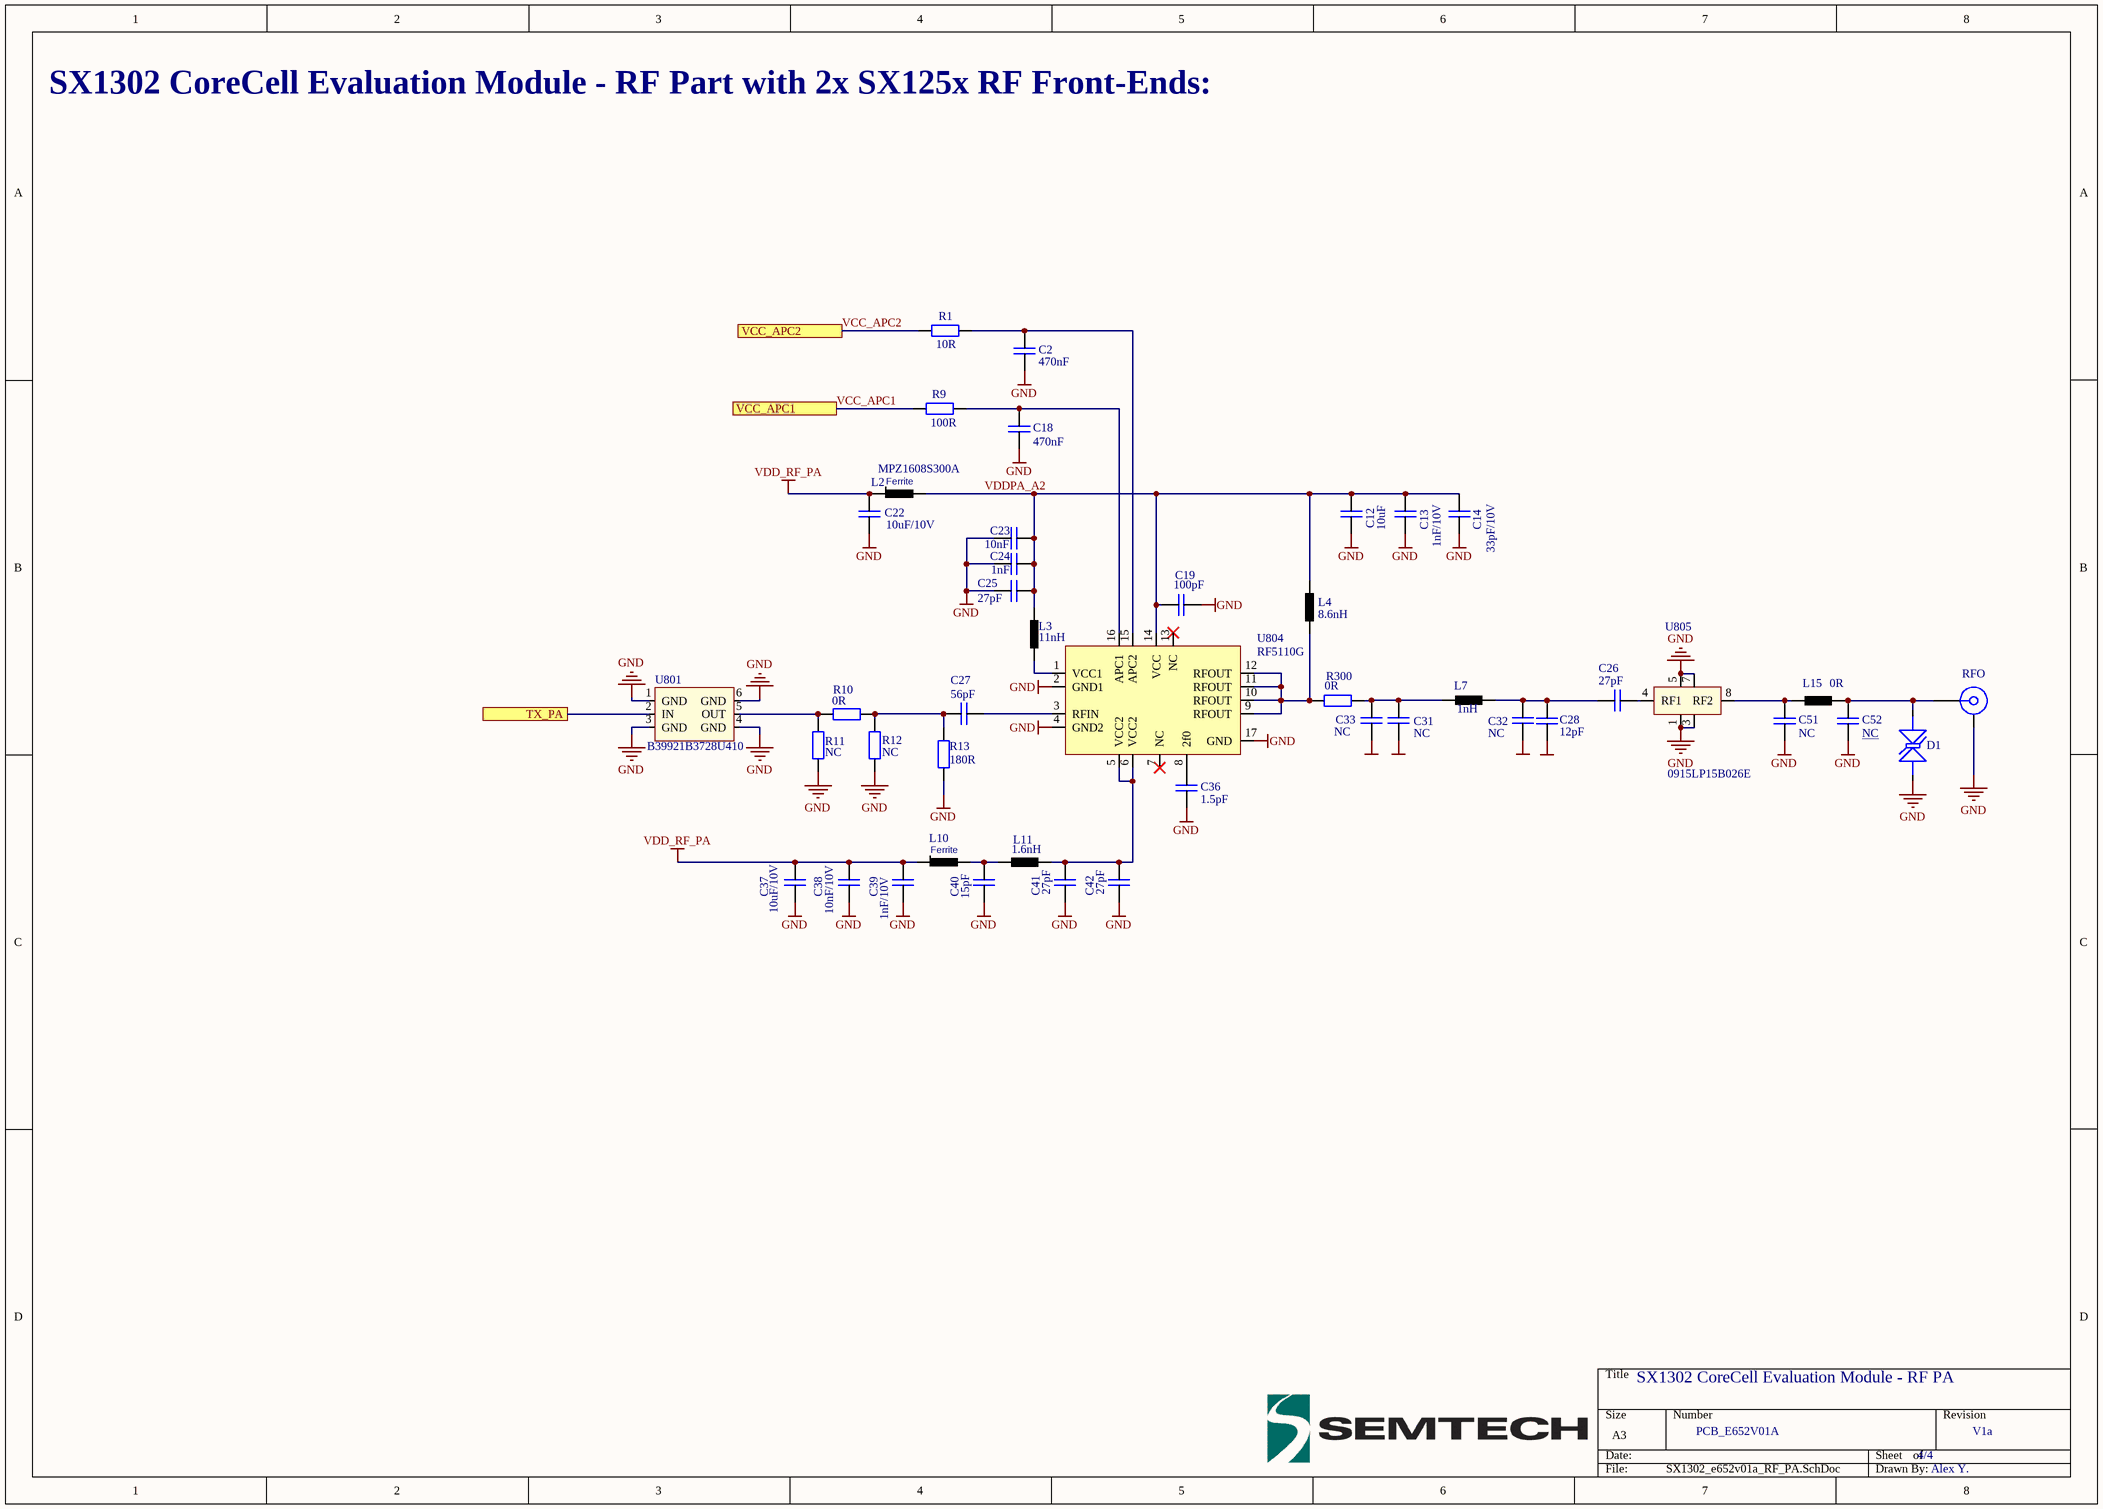
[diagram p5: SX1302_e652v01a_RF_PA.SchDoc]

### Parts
C2  470nF  [rlc_402_smd_small]
C12  value 10uF  [rlc_805_smd]
C13  1nF/10V  [rlc_402_smd_small]
C14  33pF/10V  [rlc_402_smd_small]
C18  470nF  [rlc_402_smd_small]
C19  value 100pF  [rlc_402_smd_small]
C22  10uF/10V  [rlc_805_smd]
C23  10nF  [rlc_402_smd_small]
C24  1nF  [rlc_402_smd_small]
C25  value 27pF  [rlc_402_smd_small]  (hidden comment: Cap)
C26  value 27pF  [rlc_402_smd_small]
C27  value 56pF  [rlc_402_smd_small]
C28  value 12pF  [rlc_402_smd_small]
C31  value NC  [rlc_402_smd_small]
C32  value NC  [rlc_402_smd_small]
C33  value NC  [rlc_402_smd_small]
C36  value 1.5pF  [rlc_402_smd_small]
C37  10uF/10V  [rlc_805_smd]
C38  10nF/10V  [rlc_402_smd_small]
C39  1nF/10V  [rlc_402_smd_small]
C40  value 15pF  [rlc_402_smd_small]
C41  value 27pF  [rlc_402_smd_small]
C42  value 27pF  [rlc_402_smd_small]
C51  NC  [rlc_402_smd_small]
C52  NC  [rlc_402_smd_small]
D1  RClamp2451ZA  [SLP0603P]  (value not drawn)
L2  MPZ1608S300A  [rlc_603_smd]
L3  value 11nH  [rlc_603_smd_small]
L4  value 8.6nH  [0806SQ-8N9]
L7  value 1nH  [rlc_402_smd_small]
L10  (no value)  [rlc_603_smd]
L11  value 1.6nH  [rlc_402_smd]
L15  0R  [rlc_402_smd_small]
R1  10R  [rlc_402_smd_small]
R9  100R  [rlc_402_smd_small]
R10  value 0R  [rlc_402_smd_small]  (hidden comment: Resistor)
R11  value NC  [rlc_402_smd_small]  (hidden comment: Resistor)
R12  value NC  [rlc_402_smd_small]  (hidden comment: Resistor)
R13  180R  [rlc_402_smd_small]
R300  value 0R  [rlc_402_smd_small]
RFO  32K242-40ML5  [ROS-32K242-40ML5_V _modified]  (value not drawn)
U801  PN: B39921B3728U410  [DCC6C_3.0x3.0mm]  (hidden comment: SAW Filter)
U804  RF5110G  [mlpq16_3x3mm]
U805  value 0915LP15B026E  [LP Filter Johanson]

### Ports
TX_PA, VCC_APC1, VCC_APC2

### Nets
GND: C2.1 C12.1 C13.1 C14.1 C18.1 C19.1 C22.1 C23.1 C24.1 C25.1 C28.1 C31.1 C32.1 C33.1 C36.1 C37.1 C38.1 C39.1 C40.1 C41.1 C42.1 C51.1 C52.1 D1.2(K) R11.1 R12.1 R13.1 RFO.MP U801.1(GND) U801.3(GND) U801.4(GND) U801.6(GND) U804.2(GND1) U804.4(GND2) U804.17(GND) U805.1(GND) U805.3(GND) U805.5(GND) U805.7(GND)
VDD_RF_PA: C22.2 C37.2 C38.2 C39.2 L2.1 L10.1
TX_PA: U801.2(IN) ; port TX_PA
VCC_APC1: R9.2 ; port VCC_APC1
VCC_APC2: R1.2 ; port VCC_APC2
VDDPA_A2: C12.2 C13.2 C14.2 C19.2 C23.2 C24.2 C25.2 L2.2 L3.2 L4.2 U804.14(VCC)
NetC2_2: C2.2 R1.1 U804.15(APC2)
NetC18_2: C18.2 R9.1 U804.16(APC1)
NetC26_1: C26.1 U805.4(RF1)
NetC26_2: C26.2 C28.2 C32.2 L7.2
NetC27_1: C27.1 U804.3(RFIN)
NetC27_2: C27.2 R10.1 R12.2 R13.2
NetC31_2: C31.2 C33.2 L7.1 R300.1
NetC36_2: C36.2 U804.8(2f0)
NetC40_2: C40.2 L10.2 L11.1
NetC41_2: C41.2 C42.2 L11.2 U804.5(VCC2) U804.6(VCC2)
NetC51_2: C51.2 L15.1 U805.8(RF2)
NetC52_2: C52.2 D1.1(A) L15.2 RFO.1
NetL3_1: L3.1 U804.1(VCC1)
NetL4_1: L4.1 R300.2 U804.9(RFOUT) U804.10(RFOUT) U804.11(RFOUT) U804.12(RFOUT)
NetR10_2: R10.2 R11.2 U801.5(OUT)

Not connected (* = marked no-connect by the designer): U804 7(NC)* 13(NC)*

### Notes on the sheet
- SX1302 CoreCell Evaluation Module - RF Part with 2x SX125x RF Front-Ends:
- SX1302 CoreCell Evaluation Module - RF PA
- PCB_E652V01A
- 4/4
- V1a
- Alex Y.

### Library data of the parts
C2 C12-C14 C18 C19 C22-C28 C31-C33 C36-C42 C51 C52 = 70001226: Ceramic Capacitor SMD
D1 = RClamp0531T: as D3 on sheet SX1302_e652v01a_Power&Interface&Sensors
L2 L10 = L_MPZ1608S300A: Ferrite Bead 30Ohm 10mOhm DC 5A; Manufacturer: TDK; Replacement: Yes
L3 = L_LQW15AN11NJ80D_11NH_0402: Inductance wirewound 0402; Manufacturer: Murata; Replacement: Yes
L4 = L_LQW15AN8N7J80D_8_7NH_0402: Inductance wirewound 0402; Manufacturer: Murata; Replacement: Yes
L7 = L_LQW15AN3N6D80D_3_6NH_0402: Inductance wirewound 0402; Manufacturer: Murata; Replacement: Yes
L11 = L_LQW15AN1N6D80D_1_6NH_0402: Inductance wirewound 0402; Manufacturer: Murata; Replacement: Yes
L15 = L_LQW15AN3N6D80D_3_6NH_0402: 3.6nH Inductance wirewound 0402; Manufacturer: Murata; Replacement: Yes
R1 R9 R300 = 70001106: SMD Resistor; MatNr: 70002460
R10-R12 = Resistor: Resistor SMD - IEC symbol version
R13 = 70001106: SMD Resistor; Value: 10k; MatNr: 70002460
RFO = 32K242-40ML5: as GPS on sheet SX1302_e652v01a_Power&Interface&Sensors
U801 = SAW Filter: as U901 on sheet SX1302_e652v01a_RF_Part
U804 = RF5110G: RF5110G - General Power Amplifier; Manufacturer: RFMD; Replacement: None
U805 = FILT_0915LP15A026: RF Filter - Lowpass; Manufacturer: Johanson Technology; Replacement: TBD

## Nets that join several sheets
GND: SX1302_e652v01a_Main part (29 pins), SX1302_e652v01a_Power&Interface&Sensors (84 pins), SX1302_e652v01a_RF_Part (71 pins), SX1302_e652v01a_RF_PA (39 pins)
VCCCORE12: SX1302_e652v01a_Main part (11 pins), SX1302_e652v01a_Power&Interface&Sensors (C221.2 FB208.2)
VCCIO33: SX1302_e652v01a_Main part (12 pins), SX1302_e652v01a_Power&Interface&Sensors (22 pins)
VDD_RF_125x: SX1302_e652v01a_Power&Interface&Sensors (FB201.2 P200.1), SX1302_e652v01a_RF_Part (21 pins)
VDD_RF_LNA: SX1302_e652v01a_Power&Interface&Sensors (FB203.2 P201.1), SX1302_e652v01a_RF_Part (C43.2 C44.2 L12.2)
VDD_RF_PA: SX1302_e652v01a_Power&Interface&Sensors (C9.2 C10.2 L1.2 R5.2), SX1302_e652v01a_RF_PA (6 pins)
GPIO(6): SX1302_e652v01a_Main part (U100.57), SX1302_e652v01a_Power&Interface&Sensors (CN1.38)
GPIO(10): SX1302_e652v01a_Main part (U100.51), SX1302_e652v01a_Power&Interface&Sensors (CN1.36)
HOST_CSN: SX1302_e652v01a_Main part (R103.1 U100.1), SX1302_e652v01a_Power&Interface&Sensors (CN1.24)
HOST_MISO: SX1302_e652v01a_Main part (R102.2), SX1302_e652v01a_Power&Interface&Sensors (CN1.21), SX1302_e652v01a_RF_Part (R704.2)
HOST_MOSI: SX1302_e652v01a_Main part (U100.3), SX1302_e652v01a_Power&Interface&Sensors (CN1.19), SX1302_e652v01a_RF_Part (U700.17)
HOST_SCK: SX1302_e652v01a_Main part (U100.4), SX1302_e652v01a_Power&Interface&Sensors (CN1.23), SX1302_e652v01a_RF_Part (U700.18)
PPS: SX1302_e652v01a_Main part (R108.1), SX1302_e652v01a_Power&Interface&Sensors (CN1.40 U207.4)
RADIO_A_CLK_32M: SX1302_e652v01a_Main part (R115.2), SX1302_e652v01a_RF_Part (U800.10)
RADIO_A_CSN: SX1302_e652v01a_Main part (U100.68), SX1302_e652v01a_RF_Part (U800.20)
RADIO_A_IQ(0): SX1302_e652v01a_Main part (R110.2), SX1302_e652v01a_RF_Part (U800.14)
RADIO_A_IQ(1): SX1302_e652v01a_Main part (R111.2), SX1302_e652v01a_RF_Part (U800.13)
RADIO_A_IQ(2): SX1302_e652v01a_Main part (R112.2), SX1302_e652v01a_RF_Part (R813.1 U800.11)
RADIO_A_IQ(3): SX1302_e652v01a_Main part (R113.2), SX1302_e652v01a_RF_Part (U800.15)
RADIO_A_IQ(4): SX1302_e652v01a_Main part (R114.2), SX1302_e652v01a_RF_Part (U800.12)
RADIO_A_MISO: SX1302_e652v01a_Main part (U100.42), SX1302_e652v01a_RF_Part (U800.18)
RADIO_A_MOSI: SX1302_e652v01a_Main part (U100.67), SX1302_e652v01a_RF_Part (U800.19)
RADIO_A_RESET: SX1302_e652v01a_Main part (U100.13), SX1302_e652v01a_RF_Part (D800.2)
RADIO_A_SCK: SX1302_e652v01a_Main part (U100.65), SX1302_e652v01a_RF_Part (U800.17)
RADIO_B_CLK_32M: SX1302_e652v01a_Main part (R125.1), SX1302_e652v01a_RF_Part (U900.10)
RADIO_B_CSN: SX1302_e652v01a_Main part (U100.18), SX1302_e652v01a_RF_Part (5 pins)
RADIO_B_IQ(0): SX1302_e652v01a_Main part (R120.2), SX1302_e652v01a_RF_Part (U900.14)
RADIO_B_IQ(1): SX1302_e652v01a_Main part (R121.2), SX1302_e652v01a_RF_Part (U900.13)
RADIO_B_IQ(2): SX1302_e652v01a_Main part (R122.2), SX1302_e652v01a_RF_Part (R814.1 U900.11)
RADIO_B_IQ(3): SX1302_e652v01a_Main part (R123.1), SX1302_e652v01a_RF_Part (U900.15)
RADIO_B_IQ(4): SX1302_e652v01a_Main part (R124.2), SX1302_e652v01a_RF_Part (U900.12)
RADIO_B_MISO: SX1302_e652v01a_Main part (U100.33), SX1302_e652v01a_RF_Part (U900.18)
RADIO_B_MOSI: SX1302_e652v01a_Main part (U100.19), SX1302_e652v01a_RF_Part (U900.19)
RADIO_B_RESET: SX1302_e652v01a_Main part (U100.28), SX1302_e652v01a_RF_Part (D900.2)
RADIO_B_SCK: SX1302_e652v01a_Main part (U100.21), SX1302_e652v01a_RF_Part (U900.17)
SX1261_BUSY: SX1302_e652v01a_Power&Interface&Sensors (CN1.7), SX1302_e652v01a_RF_Part (U700.14)
SX1261_DIO1: SX1302_e652v01a_Power&Interface&Sensors (CN1.11), SX1302_e652v01a_RF_Part (U700.13)
SX1261_DIO2: SX1302_e652v01a_Power&Interface&Sensors (CN1.13), SX1302_e652v01a_RF_Part (U700.12)
SX1261_NRESET: SX1302_e652v01a_Power&Interface&Sensors (CN1.15), SX1302_e652v01a_RF_Part (R703.2 U700.15)
SX1261_NSS: SX1302_e652v01a_Power&Interface&Sensors (CN1.26), SX1302_e652v01a_RF_Part (R702.2 R705.2)
SX1302_LNA_REG_EN: SX1302_e652v01a_Main part (U100.11), SX1302_e652v01a_Power&Interface&Sensors (R204.2)
SX1302_PA_REG_EN: SX1302_e652v01a_Main part (U100.12), SX1302_e652v01a_Power&Interface&Sensors (R3.2)
SX1302_RESET: SX1302_e652v01a_Main part (R101.2 U100.7), SX1302_e652v01a_Power&Interface&Sensors (CN1.16)
TX_PA: SX1302_e652v01a_RF_Part (T1.1), SX1302_e652v01a_RF_PA (U801.2)
VCC_APC1: SX1302_e652v01a_Power&Interface&Sensors (C210.1 U203.1), SX1302_e652v01a_RF_PA (R9.2)
VCC_APC2: SX1302_e652v01a_Power&Interface&Sensors (C211.1 U203.5), SX1302_e652v01a_RF_PA (R1.2)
